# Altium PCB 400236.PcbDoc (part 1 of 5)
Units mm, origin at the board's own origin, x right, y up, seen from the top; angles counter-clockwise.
Board outline 136.53 x 63.5 mm, 4 copper layers (Top Layer, Mid-Layer 1, Mid-Layer 2, Bottom Layer), stack 1.49 mm thick; 344 components, 236 nets, 1364 pads, 1393 vias.
Unrouted connection lines stored in the file: 6.
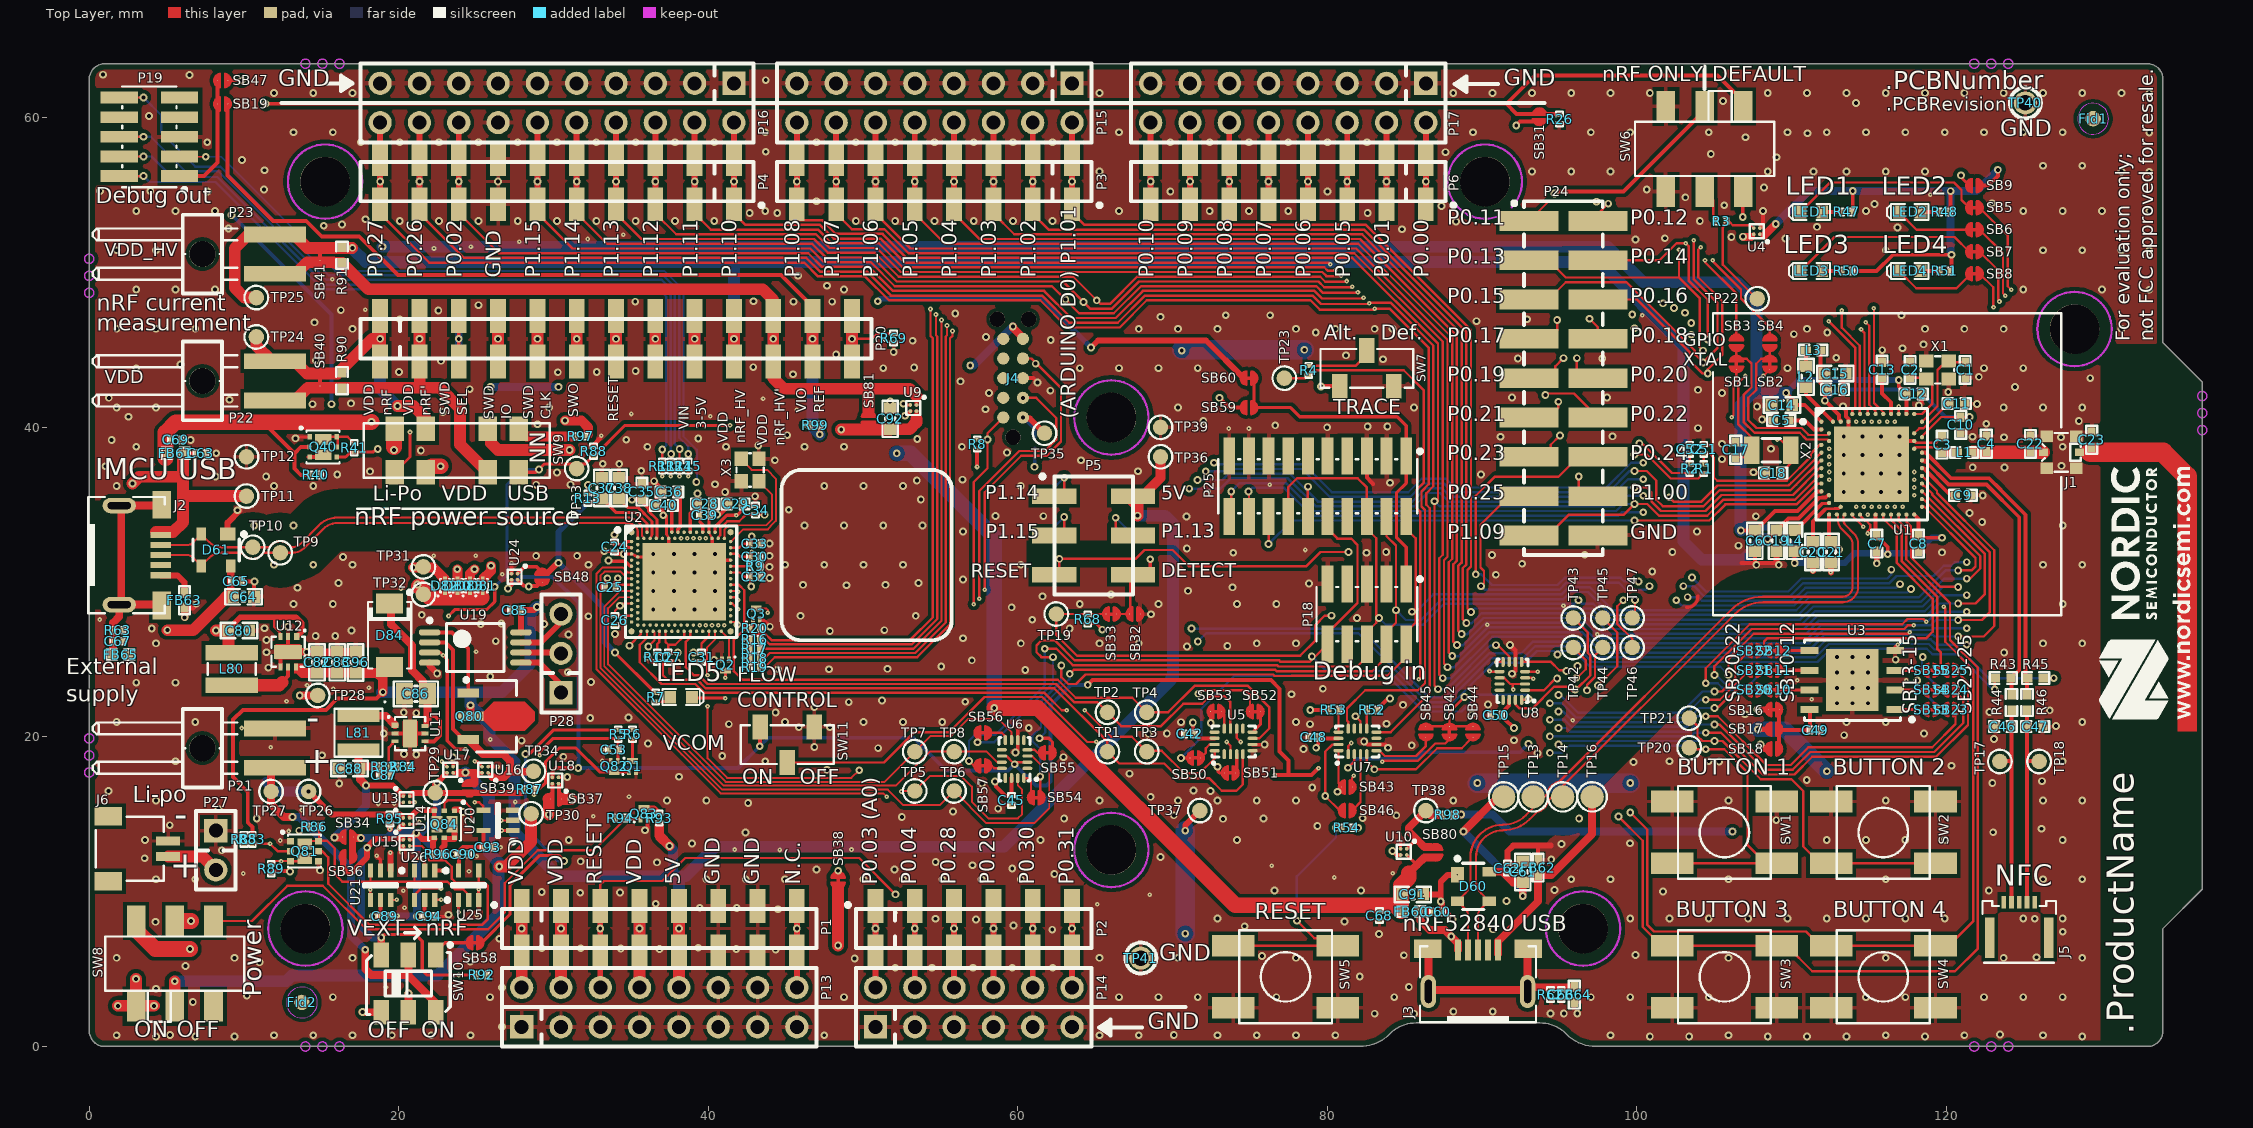
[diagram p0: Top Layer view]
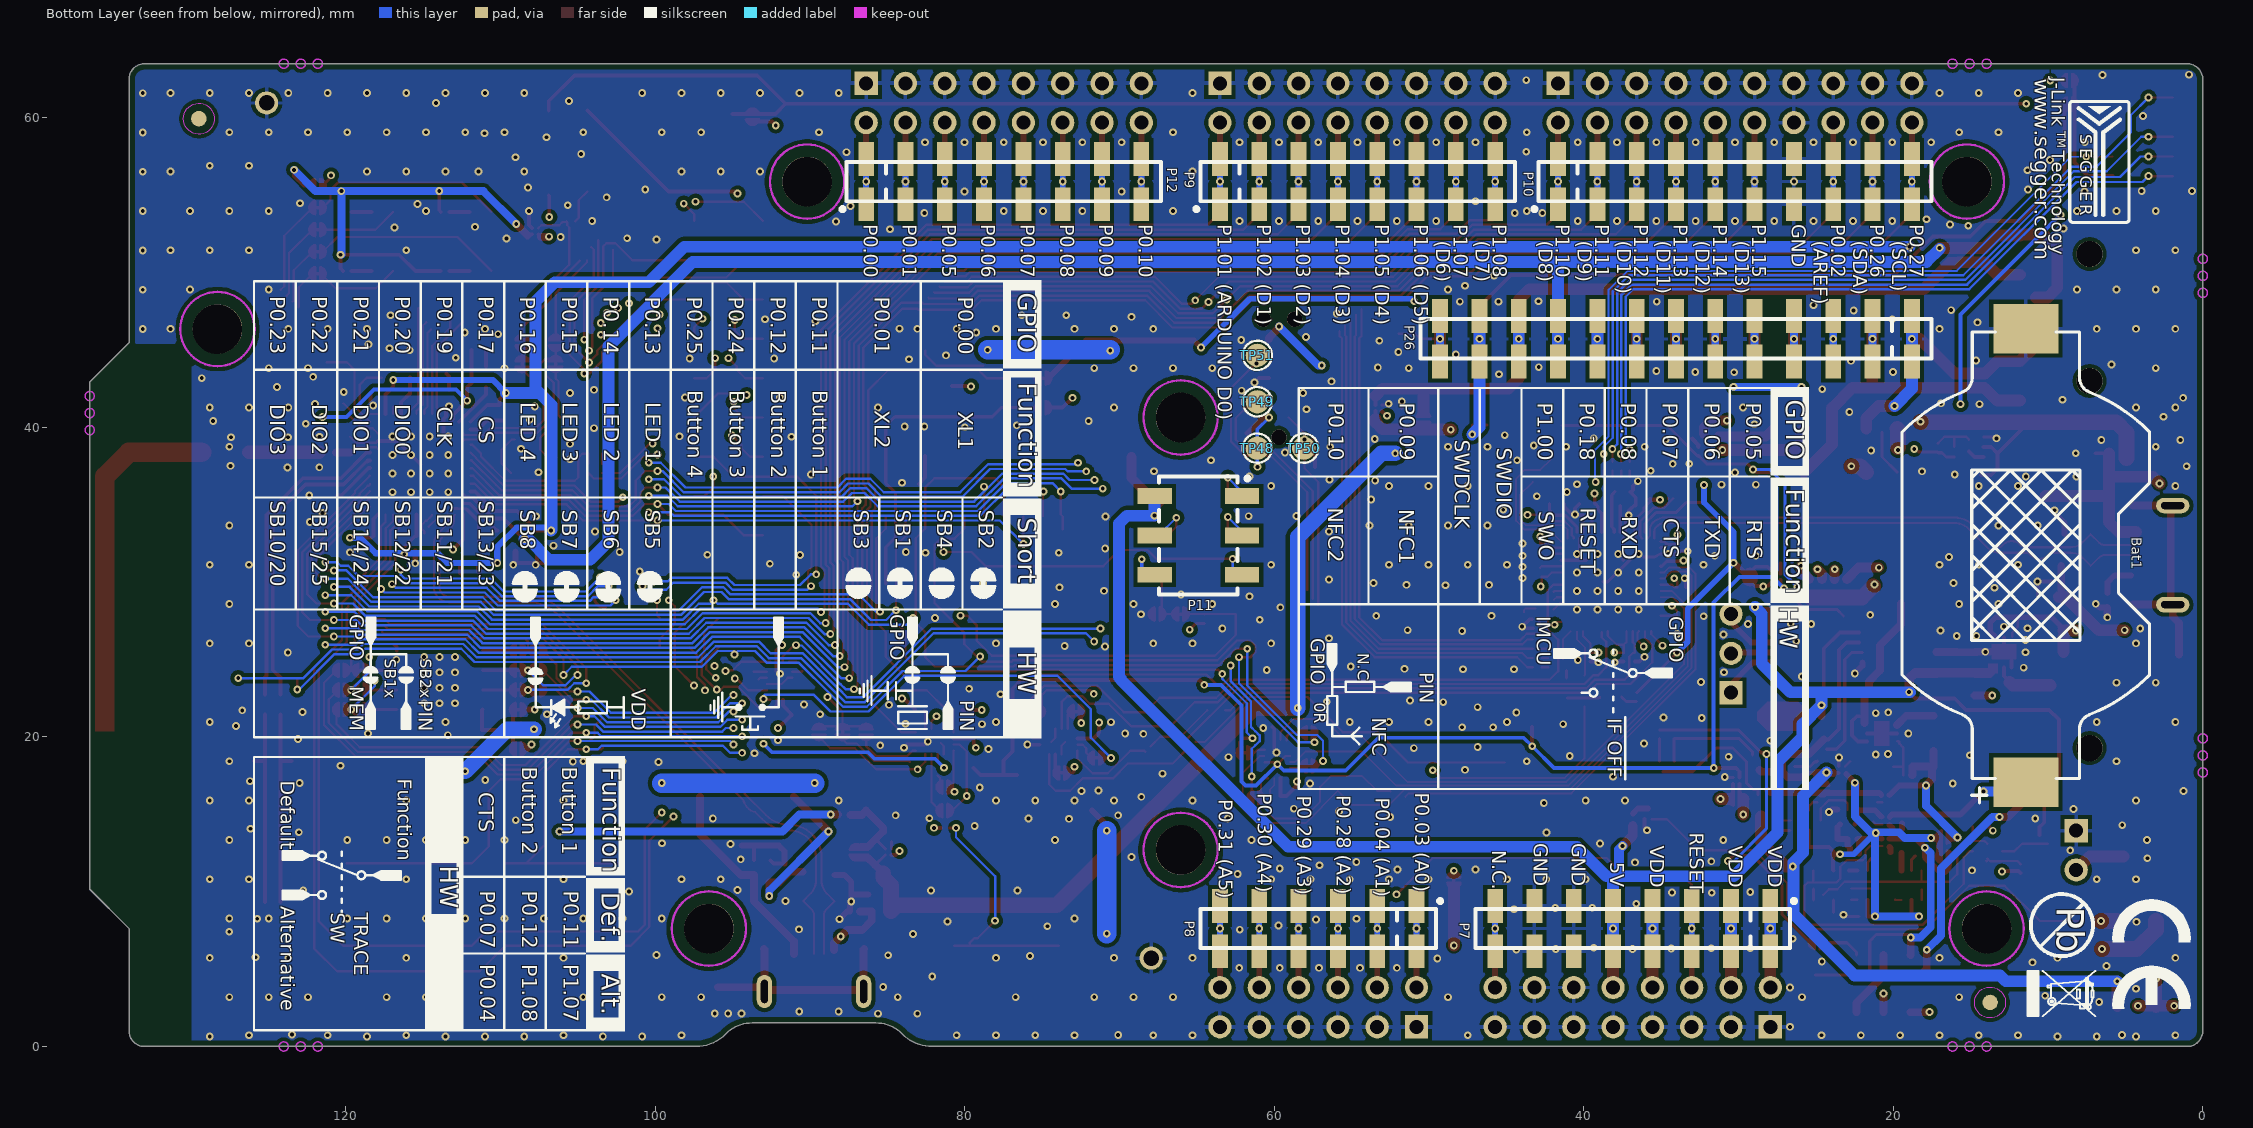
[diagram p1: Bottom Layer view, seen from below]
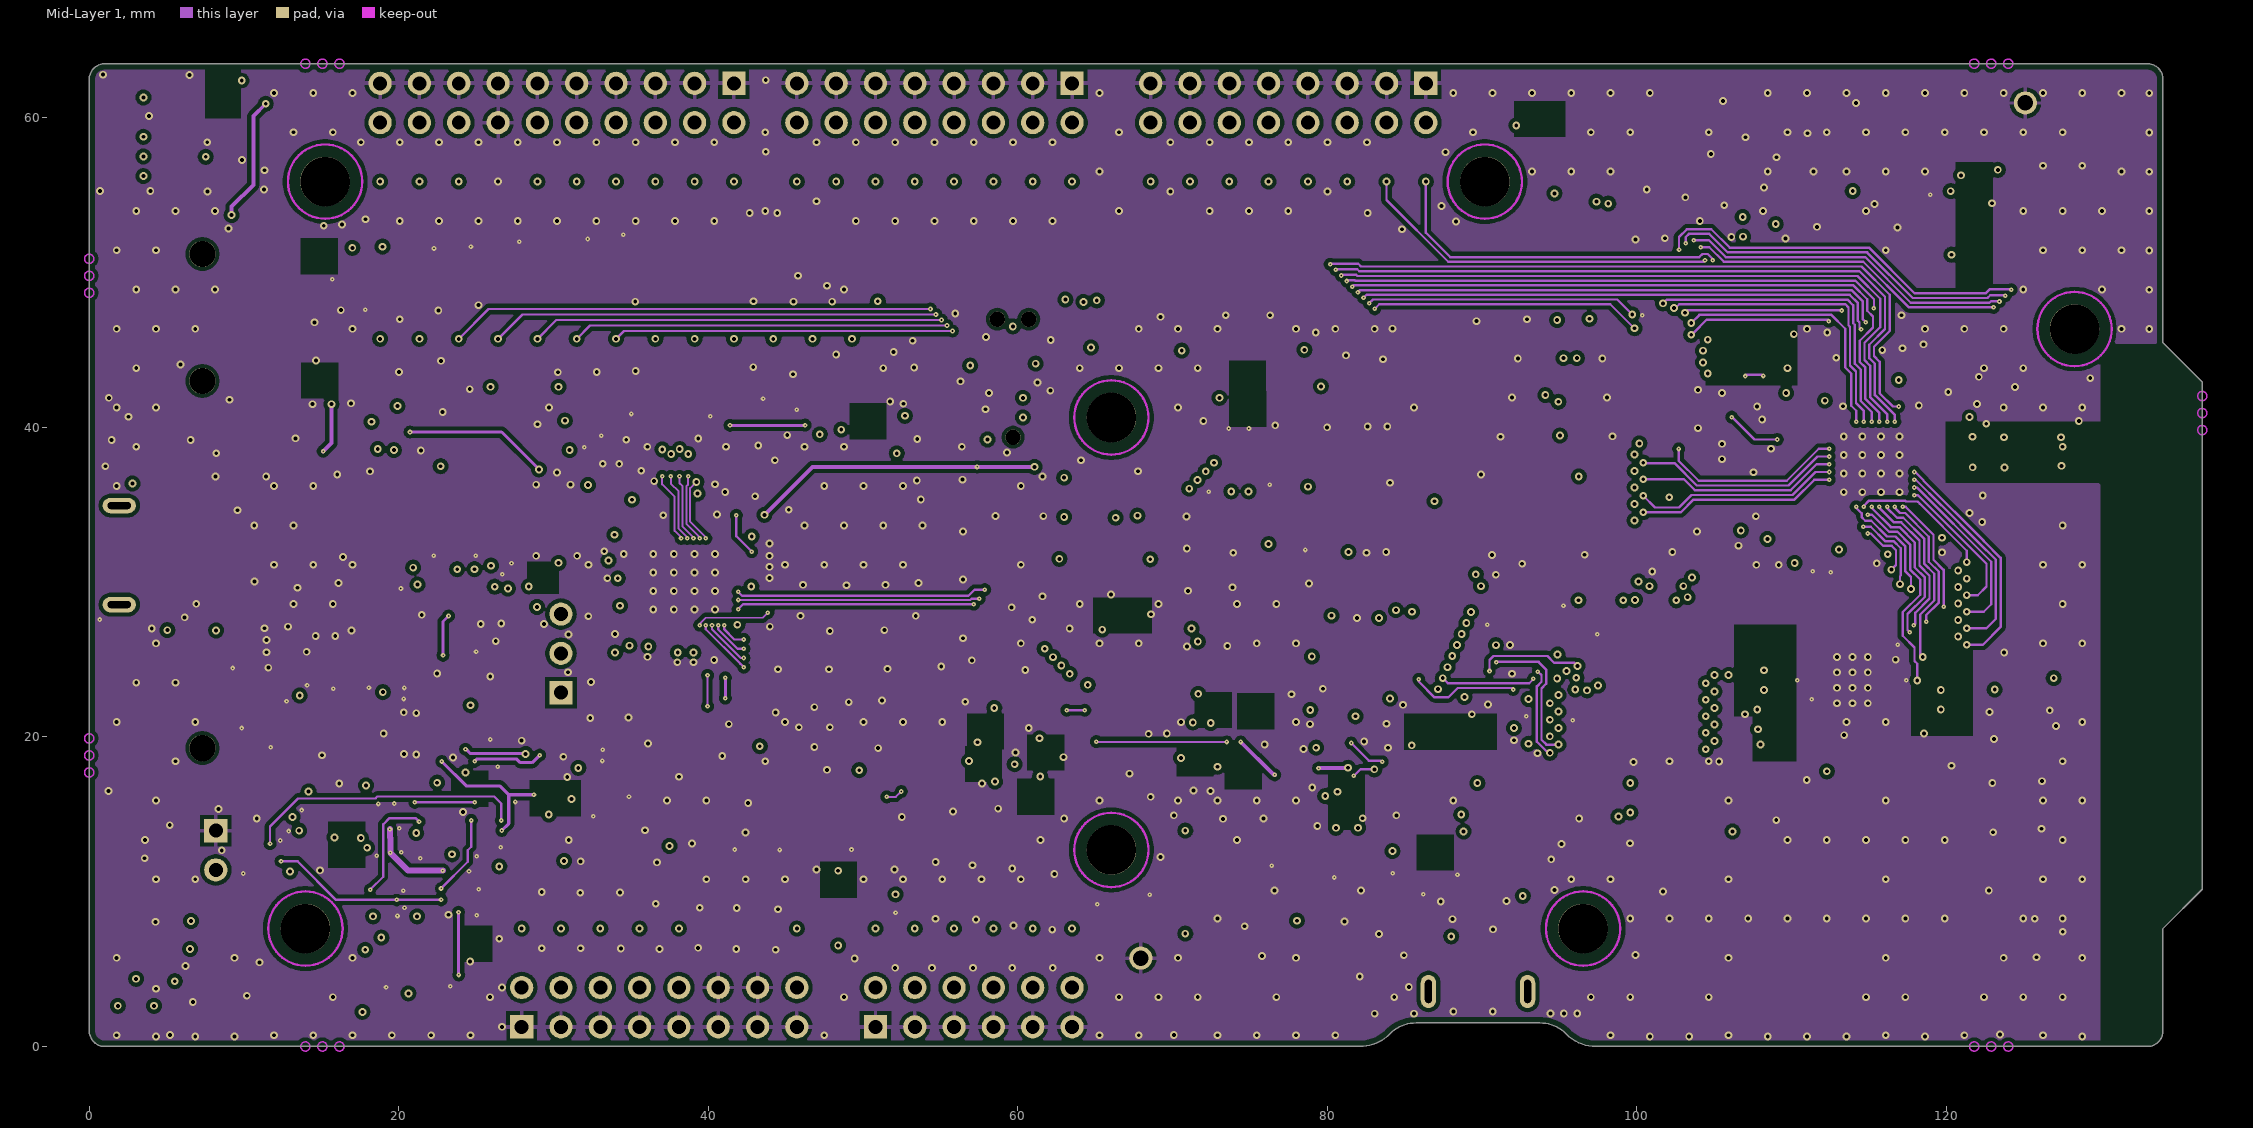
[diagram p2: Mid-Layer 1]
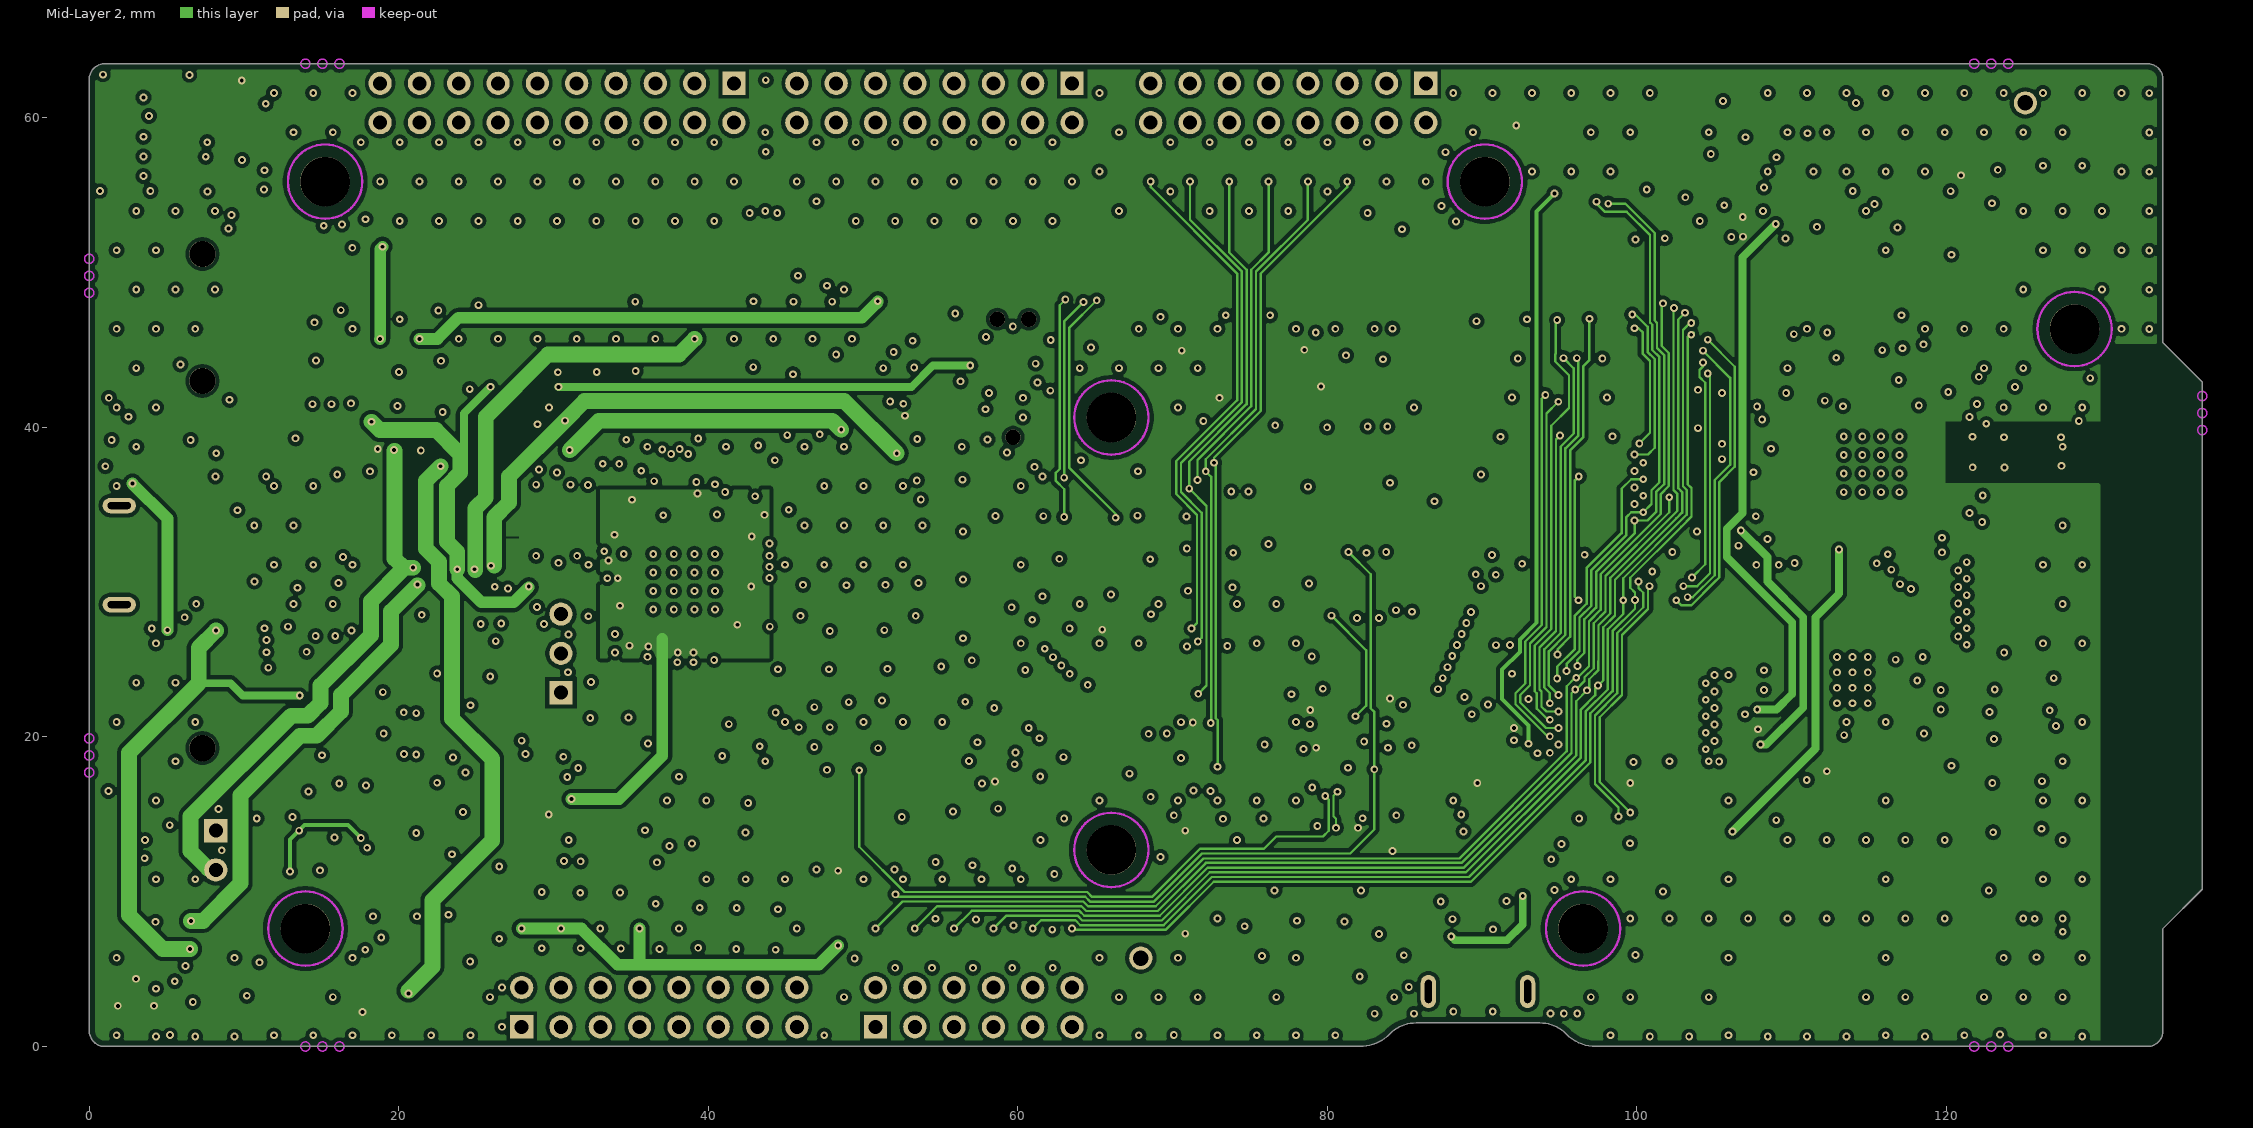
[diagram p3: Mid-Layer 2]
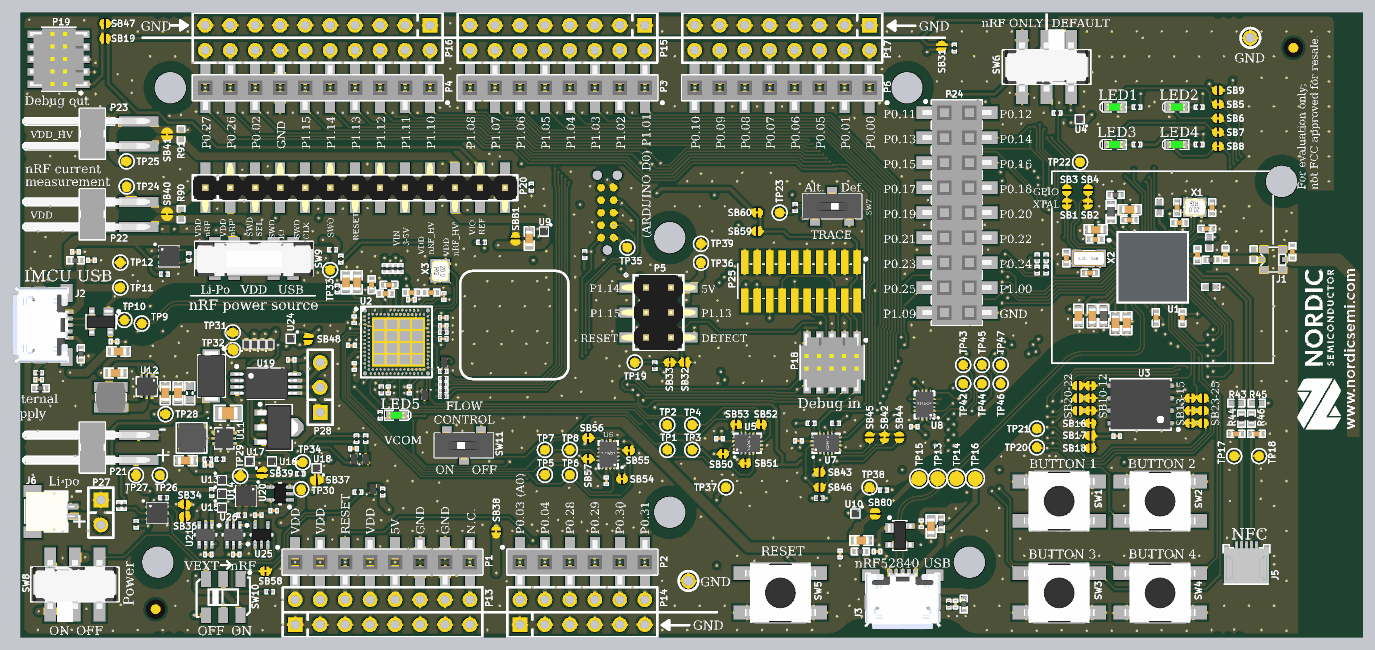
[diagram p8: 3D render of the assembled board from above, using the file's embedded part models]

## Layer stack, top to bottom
Top Solder: solder mask 0.025, Solder Resist, Dk 3.5
Top Layer: signal copper 0.035
Dielectric1: prepreg 0.075, FR-4, Dk 3.72
Mid-Layer 1: signal copper 0.035
Dielectric2: core 1.2, FR-4, Dk 3.72
Mid-Layer 2: signal copper 0.035
Dielectric3: prepreg 0.075, FR-4, Dk 3.72
Bottom Layer: signal copper 0.035
Bottom Solder: solder mask 0.025, Solder Resist, Dk 3.5

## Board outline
1.016,0 82.099,0 ccw(c82.099,2.717) 84.02,0.796 84.187,0.962 cw(c85.729,-0.876) 85.729,1.524 93.729,1.524 cw(c93.729,-0.876) 95.272,0.962 95.439,0.796 ccw(c97.36,2.717) 97.36,0 132.969,0 ccw(c132.969,1.016) 133.985,1.016 133.985,7.62 136.525,10.16 136.525,42.926 133.985,45.466 133.985,62.484 ccw(c132.969,62.484) 132.969,63.5 1.016,63.5 ccw(c1.016,62.484) 0,62.484 0,1.016 ccw(c1.016,1.016)

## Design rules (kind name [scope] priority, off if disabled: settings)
BoardOutlineClearance [All] p1: gap=0.381 ignorepadtopadclearanceinfootprint=FALSE
Clearance Microvia_Clearance [AsMM(ViaDiameter) = 0.3 vs AsMM(ViaDiameter) = 0.3] p1: gap=0.1 ignorepadtopadclearanceinfootprint=FALSE
Clearance USB_Poly_Clearance [InNamedPolygon('Top_Layer-GND') vs InDifferentialPair('D') or InDifferentialPair('IMCU')] p2: gap=1.778 ignorepadtopadclearanceinfootprint=FALSE
Clearance "NPTH clearance" [Not PadIsPlated And HoleSize > 0] p3: gap=0.229 ignorepadtopadclearanceinfootprint=FALSE except(0: Arc-Hole Track-Hole SMDPad-Hole THPad-Hole Via-Hole Fill-Hole Poly-Hole Region-Hole Text-Hole)
Clearance USB_Clearance [(InDifferentialPairClass('All Differential Pairs'))] p4: gap=0.125 ignorepadtopadclearanceinfootprint=FALSE
Clearance ANT_Clerance [InNet('ANT') or InNet('RF')] p5: gap=0.199 ignorepadtopadclearanceinfootprint=FALSE
Clearance Polygon_Clearance [(InNamedPolygon('Top_Layer-GND')) or (InNamedPolygon('Mid_Layer_1-GND')) or (InNamedPolygon('Mid_Layer_2-VDD')) or (InNamedPolygon('Mid_Layer_2-VDD_IMCU')) or (InNamedPolygon('Bottom_Layer-GND'))] p6: gap=0.254 ignorepadtopadclearanceinfootprint=FALSE except(0: Arc-Hole Track-Hole SMDPad-Hole THPad-Hole Via-Hole Fill-Hole Poly-Hole Region-Hole Text-Hole)
Clearance SB_Clearance [HasFootprint('Solderbridge') or HasFootprint('QFN40P180X140X55-10N')] p7: gap=0.127 ignorepadtopadclearanceinfootprint=FALSE except(0: Arc-Hole Track-Hole SMDPad-Hole THPad-Hole Via-Hole Fill-Hole Poly-Hole Region-Hole Text-Hole)
Clearance CSP_Clearance [HasFootprint('BGA4C40P2X2_76X76X62')] p8: gap=0.127 ignorepadtopadclearanceinfootprint=FALSE except(0: Arc-Hole Track-Hole SMDPad-Hole THPad-Hole Via-Hole Fill-Hole Poly-Hole Region-Hole Text-Hole)
Clearance P23_Clearance [HasFootprint('FPC_05P-0.5mm-RA-SMD')] p9: gap=0.127 ignorepadtopadclearanceinfootprint=FALSE except(0: Arc-Hole Track-Hole SMDPad-Hole THPad-Hole Via-Hole Fill-Hole Poly-Hole Region-Hole Text-Hole)
Clearance PSON35P100X50-8N_Clearance [HasFootprint('PSON35P100X50-8N')] p10: gap=0.15 ignorepadtopadclearanceinfootprint=FALSE except(0: Arc-Hole Track-Hole SMDPad-Hole THPad-Hole Via-Hole Fill-Hole Poly-Hole Region-Hole Text-Hole)
Clearance Top_layer_Clearance [All vs OnLayer('Top Layer')] p11: gap=0.125 ignorepadtopadclearanceinfootprint=FALSE
Clearance [All] p12: gap=0.125 ignorepadtopadclearanceinfootprint=FALSE
ComponentClearance [All] p1 off: gap=0.254 collisioncheckmode=3 verticalgap=0.254 showdistances=FALSE
DiffPairsRouting [All] p1: maxlimit=0.193 minlimit=0.191 mostfreqgap=0.193 toplayer_minwidth=0.15 toplayer_maxwidth=0.165 toplayer_prefwidth=0.165 midlayer1_minwidth=0.15 midlayer1_maxwidth=0.165 midlayer1_prefwidth=0.165 midlayer2_minwidth=0.15 midlayer2_maxwidth=0.165 midlayer2_prefwidth=0.165 bottomlayer_minwidth=0.15 bottomlayer_maxwidth=0.165 bottomlayer_prefwidth=0.165 maxuncoupledlength=12.7
FabricationTestPointUsage TestPointUsage [All] p1: valid=0 allowmultiple=FALSE
FabricationTestpoint Testpoint [All] p1: side=3 testpointundercomponent=TRUE minsize=1.016 maxsize=2.54 preferedsize=1.524 minholesize=0 maxholesize=1.016 preferedholesize=0.813 testpointgrid=0.025 allowsidetop=TRUE allowsidebottom=TRUE usegrid=TRUE gridtolerance=0
Height [All] p1 off: minheight=0 maxheight=25.4 prefheight=12.7
HoleSize [All] p1: absolutevalues=TRUE maxlimit=5 minlimit=0.1 maxpercent=80.000 minpercent=20.000
MinimumAnnularRing [All] p1 off: minimumring=0.152
NetAntennae NetAntennae_ANT [InNet('ANT')] p1: netantennaetolerance=40
NetAntennae [All] p2 off: netantennaetolerance=0
PolygonConnect PolygonConnect_1 [isVia and innet(gnd) or isVia and innet('VDD') or HasFootprint('COAXIAL-SWF') or isVia and innet('VDD_IMCU')] p1: connectstyle=Direct reliefconductorwidth=0.254 reliefentries=4 polygonreliefangle="90 Angle" airgapwidth=0.254
PolygonConnect [All] p2: connectstyle=Relief reliefconductorwidth=0.254 reliefentries=4 polygonreliefangle="90 Angle" airgapwidth=0.254
RoutingVias [All] p1: holewidth=0.25 width=0.5 viastyle="Through Hole" minholewidth=0.1 minwidth=0.3 maxholewidth=0.305 maxwidth=0.61
SilkToSolderMaskClearance SilkscreenOverComponentPads [IsPad] p1: minsilkscreentomaskgap=0.254 clearancetoexposedcopper=TRUE
SolderMaskExpansion SolderMaskExpansion_1 [isVia] p1: expansion=0.102 istentingtop=TRUE
SolderMaskExpansion [All] p2: expansion=0.076 istentingtop=FALSE
UnpouredPolygon [All] p1 off:
Width Width_Diff [(InDifferentialPairClass('All Differential Pairs'))] p1: maxlimit=0.165 minlimit=0.165 preferedwidth=0.165
Width [All] p2: maxlimit=10.16 minlimit=0.102 preferedwidth=0.152 minimp=50.000000 maximp=50.000000 favimp=50.000000
21 further rules are at their usual default settings.

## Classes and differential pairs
component class pca10056_sheet6_power_supply: Bat1 C53 C80 C82 C83 C85 C86 C87 C88 C89 C90 C91 C92 C93 C94 C96 D80 D81 D82 D83 D84 L80 L81 P21 P22 P23 Q1 Q80 Q81 Q82 Q83 Q84 R5 R6 R82 R83 R84 R85 R86 R87 R88 R89 R90 R91 R92 R93 R94 R95 R96 R97 R98 R99 SB34 SB36 SB37 SB38 SB39 SB40 SB41 SB48 SB58 SB80 SB81 SW8 SW9 SW10 TP24 TP25 TP26 TP27 TP28 TP29 TP30 TP32 TP33 TP34 TP35 TP36 TP37 TP38 TP39 TP40 TP41 U9 U10 U11 U12 U13 U14 U15 U16 U17 U18 U19 U20 U21 U24 U25 U26
component class pca10056_sheet5_connectors: C60 C61 C62 C63 C64 C65 C66 C67 C68 C69 D60 D61 FB60 FB61 FB62 FB63 FB64 FB65 J2 J3 J5 J6 P1 P2 P3 P4 P5 P6 P7 P8 P9 P10 P11 P12 P13 P14 P15 P16 P17 P18 P19 P20 P24 P25 P26 P27 R62 R63 R68 R69 SB19 SB32 SB33 SB47 SB59 SB60 TP9 TP10 TP11 TP12 TP13 TP14 TP15 TP16 TP17 TP18 TP19 TP31 TP42 TP43 TP44 TP45 TP46 TP47
component class pca10056_sheet4_misc: C42 C45 C46 C47 C48 C49 C50 LED1 LED2 LED3 LED4 P28 Q40 R3 R4 R26 R40 R41 R44 R46 R47 R48 R50 R51 R52 R53 R54 SB5 SB6 SB7 SB8 SB9 SB16 SB17 SB18 SB31 SB42 SB43 SB44 SB45 SB46 SB50 SB51 SB52 SB53 SB54 SB55 SB56 SB57 SW1 SW2 SW3 SW4 SW5 SW6 SW7 SW11 TP1 TP2 TP3 TP4 TP5 TP6 TP7 TP8 TP20 TP21 TP22 TP23 U3 U4 U5 U6 U7 U8
component class pca10056_sheet3_interface_mcu: C24 C25 C26 C27 C28 C29 C30 C31 C32 C33 C34 C35 C36 C37 C38 C39 C40 J4 LED5 Q2 Q3 R7 R8 R9 R10 R11 R12 R13 R14 R15 R16 R17 R18 R19 R20 TP48 TP49 TP50 TP51 U2 X3
differential pair IMCU: +IMCU_P -IMCU_N
differential pair D: +D_P -D_N

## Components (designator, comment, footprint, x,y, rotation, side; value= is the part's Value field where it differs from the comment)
Bat1 "Bat Holder CR2032" L-KLS5-CR2032-23-B1 11.43,31.735 r90 bottom locked
C1 "12pF" CAPC1005X04L 121.203,43.713 r270 top
C2 "12pF" CAPC1005X04L 117.647,43.713 r90 top
C3 "0.8pF" CAPC1005X04L 119.715,38.893 r270 top
C4 "0.5pF" CAPC1005X04L 122.57,38.938 r270 top
C5 "100nF" CAPC1005X04L 109.324,40.455 r180 top
C6 "4.7µF" CAPC1608X06L 107.613,32.667 r270 top
C7 "100nF" CAPC1005X04L 115.49,32.492 r270 top
C8 "100nF" CAPC1005X04L 118.189,32.492 r270 top
C9 "N.C." CAPC1005X04L_NC 121.064,35.617 r0 top
C10 "N.C." CAPC1005X04L_NC 120.919,40.157 r90 top
C11 "100pF" CAPC1005X04L 120.664,41.542 r0 top
C12 "100nF" CAPC1005X04L 117.889,42.167 r0 top
C13 "N.C." CAPC1005X04L_NC 115.839,43.717 r90 top
C14 "1.0µF" CAPC1608X06L 109.364,41.444 r180 top
C15 "1.0µF" CAPC1608X06L 112.814,43.481 r180 top
C16 "47nF" CAPC1005X04L 112.801,42.443 r0 top
C17 "12pF" CAPC1005X04L 106.385,38.55 r270 top
C18 "12pF" CAPC1005X04L 108.798,37.052 r0 top
C19 "4.7µF" CAPC1608X06L 109.014,32.667 r270 top
C20 "4.7µF" CAPC1608X06L 111.364,31.942 r270 top
C21 "4.7µF" CAPC1608X06L 112.539,31.942 r270 top
C22 "N.C." CAPC1005X04L_NC 125.423,38.935 r90 top
C23 "1.2pF" CAPC1005X04L 129.379,39.204 r90 top
C24 "100nF" CAPC0603X03L_C 33.939,32.277 r270 top
C25 "100nF" CAPC0603X03L_C 33.664,29.677 r180 top
C26 "100nF" CAPC0603X03L_C 33.964,27.527 r270 top
C27 "100nF" CAPC0603X03L_C 37.415,25.152 r270 top
C28 "1.0µF" CAPC1005X04L 39.789,35.052 r0 top
C29 "1.0µF" CAPC1005X04L 41.764,35.052 r0 top
C30 "2.2nF" CAPC0603X03L_C 43,31.652 r0 top
C31 "100nF" CAPC0603X03L_C 39.564,25.152 r270 top
C32 "100nF" CAPC0603X03L_C 43,30.352 r0 top
C33 "100nF" CAPC0603X03L_C 43,32.491 r0 top
C34 "100nF" CAPC0603X03L_C 43.05,34.65 r90 top
C35 "1.0µF" CAPC1005X04L 35.714,35.852 r270 top
C36 "1.0µF" CAPC1005X04L 37.489,35.832 r0 top
C37 "4.7µF" CAPC1608X06L 33.114,36.082 r90 top
C38 "4.7µF" CAPC1608X06L 34.239,36.082 r90 top
C39 "100nF" CAPC0603X03L_C 39.758,34.327 r0 top
C40 "1.0µF" CAPC1005X04L 37.139,34.957 r0 top
C42 "100nF" CAPC0603X03L_C 71.095,20.193 r0 top
C45 "100nF" CAPC0603X03L_C 59.588,15.9 r90 top
C46 "300pF" CAPC1005X04L 123.647,20.669 r180 top
C47 "300pF" CAPC1005X04L 125.73,20.669 r180 top
C48 "100nF" CAPC0603X03L_C 79.121,19.964 r0 top
C49 "100nF" CAPC0603X03L_C 111.506,20.447 r180 top
C50 "100nF" CAPC0603X03L_C 90.907,21.412 r0 top
C51 "N.C." CAPC0603X03L_C_NC 104.318,38.583 r270 top
C52 "N.C." CAPC0603X03L_C_NC 103.403,38.583 r270 top
C53 "10nF" CAPC0603X03L_C 33.875,19.175 r0 top
C60 "10nF" CAPC0603X03L_C 87.122,8.712 r180 top
C61 "10µF" CAPC1608X06L 92.623,11.278 r270 top
C62 "100nF" CAPC0603X03L_C 91.632,11.532 r270 top
C63 "10nF" CAPC0603X03L_C 7.219,38.329 r0 top
C64 "10µF" CAPC1608X06L 9.972,29.058 r180 top
C65 "100nF" CAPC0603X03L_C 9.515,30.074 r180 top
C66 "4.7nF" CAPC0603X03L_C 95.104,3.355 r90 top
C67 "4.7nF" CAPC0603X03L_C 1.85,26.187 r180 top
C68 "100nF" CAPC0603X03L_C 83.363,8.458 r90 top
C69 "100nF" CAPC0603X03L_C 5.588,39.192 r180 top
C80 "10µF" CAPC1608X06L 9.675,26.875 r180 top
C82 "10µF" CAPC1608X06L 14.725,24.825 r270 top
C83 "10µF" CAPC1608X06L 16.025,24.825 r270 top
C85 "100nF" CAPC0603X03L_C 27.534,28.194 r0 top
C86 "4.7µF" CAPC2012X11L 21.107,22.784 r0 top
C87 "150pF" CAPC0603X03L_C 19.075,17.526 r180 top
C88 "10µF" CAPC1608X06L 16.815,17.958 r0 top
C89 "100nF" CAPC0603X03L_C 19.101,8.407 r180 top
C90 "100nF" CAPC0603X03L_C 24.181,12.421 r180 top
C91 "1.0µF" CAPC1608X06L 85.522,9.83 r180 top
C92 "1.0µF" CAPC1608X06L 51.75,40.55 r270 top
C93 "100nF" CAPC0603X03L_C 25.756,12.878 r180 top
C94 "100nF" CAPC0603X03L_C 21.946,8.407 r180 top
C96 "N.C." CAPC1608X06L_NC 17.215,24.815 r270 top
D60 "PRTR5V0U2X" SOT190P230X110-4L 89.427,10.34 r0 top
D61 "PRTR5V0U2X" SOT190P230X110-4L 8.194,32.08 r270 top
D80 "NSR0620P2T5G" SODFL100X40-2N 23.8,29.766 r90 top
D81 "NSR0620P2T5G" SODFL100X40-2N 25.425,29.766 r90 top
D82 "NSR0620P2T5G" SODFL100X40-2N 22.987,29.766 r90 top
D83 "NSR0620P2T5G" SODFL100X40-2N 24.613,29.766 r90 top
D84 "LS14" SODFL500X108-2N 19.407,26.568 r270 top
FB60 "120R/0.55A" INDC1005X04L 85.42,8.712 r180 top
FB61 "120R/0.55A" INDC1005X04L 5.588,38.329 r180 top
FB62 "120R/0.55A" INDC1005X04L 93.614,11.558 r90 top
FB63 "120R/0.55A" INDC1005X04L 6.147,28.829 r270 top
FB64 "120R/0.55A" INDC1005X04L 95.942,3.355 r270 top
FB65 "120R/0.55A" INDC1005X04L 2.021,25.317 r0 top
Fid1 "Fiducial mark" Fiducial 129.471,59.944 r180 top value=N.A.
Fid2 "Fiducial mark" Fiducial 13.743,2.845 r0 top value=N.A.
J1 "MM8130-2600" COAXIAL-SWF 127.423,38.391 r90 top
J2 "MicroUSB-B" USB-Micro-B-RA-SMD-PiP_Allen 4.619,31.75 r0 top
J3 "MicroUSB-B" USB-Micro-B-RA-SMD-PiP_Allen 89.729,6.232 r90 top
J4 "TC2050-IDC" TC2050-IDC-NLFP 59.69,43.18 r90 top locked
J5 "FPC 0.5mm RA SMD" FPC_05P-0.5mm-RA-SMD 123.698,9.328 r0 top
J6 "HDR-2, 1mm" SM02B-SRSS-TB 5.105,12.776 r270 top
L1 "4.7nH" INDC1005X04L 121.138,38.385 r0 top
L2 "10µH" INDC1608X06L 110.914,43.267 r270 top
L3 "15nH" INDC1005X04L 111.389,44.992 r180 top
L4 "10µH" INDC1608X06L 110.189,32.667 r90 top
L80 "4.7µH" VLS3012HBX 9.2,24.4 r270 top
L81 "4.7µH" TY-NR3015 17.399,20.269 r270 top
LED1 "L0603G" LED_0603_G 111.273,53.917 r0 top
LED2 "L0603G" LED_0603_G 117.623,53.917 r0 top
LED3 "L0603G" LED_0603_G 111.273,50.107 r0 top
LED4 "L0603G" LED_0603_G 117.623,50.107 r0 top
LED5 "L0603G" LED_0603_G 38.239,22.575 r180 top
P1 "Socket 1x8" SOCKET_1x8_SMD 27.94,7.62 r0 top locked
P2 "Socket 1x6" SOCKET_1x6_SMD 50.8,7.62 r0 top locked
P3 "Socket 1x8" SOCKET_1x8_SMD 63.5,55.88 r180 top locked
P4 "Socket 1x10" SOCKET_1x10_SMD 41.656,55.88 r180 top locked
P5 "Pin Hdr 2x3" HDR_2x3-SMD 64.897,33.02 r270 top locked
P6 "Socket 1x8" SOCKET_1x8_SMD 86.36,55.88 r180 top locked
P7 "Pin List 1x8" LIST_1x8_SMD-NC 27.94,7.62 r0 bottom locked
P8 "Pin List 1x6" LIST_1x6_SMD-NC 50.8,7.62 r0 bottom locked
P9 "Pin List 1x8" LIST_1x8_SMD-NC 63.5,55.88 r180 bottom locked
P10 "Pin List 1x10" LIST_1x10_SMD-NC 41.656,55.88 r180 bottom locked
P11 "Socket 2x3" SOCKET_2x3_SMD-2.54mm-NC 64.897,33.02 r90 bottom
P12 "Pin List 1x8" LIST_1x8_SMD-NC 86.36,55.88 r180 bottom locked
P13 "Pin Header 2x8" HDR_2x8-NC 36.83,2.54 r0 top locked
P14 "Pin Header 2x6" HDR_2x6-NC 57.15,2.54 r0 top locked
P15 "Pin Header 2x8" HDR_2x8-NC 54.61,60.96 r180 top locked
P16 "Pin Header 2x10" HDR_2x10-NC 30.226,60.96 r180 top locked
P17 "Pin Header 2x8" HDR_2x8-NC 77.47,60.96 r180 top locked
P18 "Pin Header 2x5, 1.27mm" HDR_2x5-SMD-1.27mm-K 82.55,27.94 r180 top locked
P19 "Pin Header 2x5, 1.27mm" HDR_2x5-SMD-1.27mm-K 3.886,58.776 r90 top
P20 "Pin List 1x13" LIST_1x13_SMD 18.796,45.72 r0 top locked
P21 "Pin List 1x2, Angled" LIST_ANG_1x2-SMD-2.54MM 11.811,19.279 r270 top
P22 "Pin List 1x2, Angled" LIST_ANG_1x2-SMD-2.54MM 11.811,43 r270 top
P23 "Pin List 1x2, Angled" LIST_ANG_1x2-SMD-2.54MM 11.811,51.2 r270 top
P24 "Socket 2x9" SOCKET_2x9_SMD-2.54mm-Mirrored 95.25,43.18 r270 top locked
P25 "Pin Header 2x10, 1.27mm" HDR_2x10-SMD-1.27mm-NC 79.375,36.195 r180 top locked
P26 "Socket 1x13" LIST_1x13_SMD-NC 18.796,45.72 r0 bottom locked
P27 "Pin List 1x2" LIST_1x2-NC 8.179,12.675 r270 top locked
P28 "Pin List 1x3" LIST_1x3-NC 30.48,25.4 r90 top locked
Q1 "RV2C010UNT2L" DFN65P100X40-3L 35.1,18.1 r90 top
Q2 "RV2C010UNT2L" DFN65P100X40-3L 41.1,24.65 r270 top
Q3 "RV2C010UNT2L" DFN65P100X40-3L 43.1,27.95 r90 top
Q40 "PMCPB5530" PMCPB5530X 15.113,38.735 r0 top
Q80 "FCX690BTA" SOT89-150P409X160-3N 26.289,21.336 r0 top
Q81 "TSM250N02DCQ RFG" DFN65P200X200X80_HS-6N 13.919,12.624 r0 top
Q82 "RV2C010UNT2L" DFN65P100X40-3L 33.925,18.1 r270 top
Q83 "RV2C010UNT2L" DFN65P100X40-3L 35.839,15.037 r90 top
Q84 "PMCPB5530" PMCPB5530X 22.951,14.356 r270 top
R1 "0R" RESC0603X03L_C 104.318,37.338 r90 top
R2 "0R" RESC0603X03L_C 103.403,37.338 r90 top
R3 "10k" RESC0603X03L_C 105.435,53.315 r180 top
R4 "10k" RESC0603X03L_C 78.791,43.688 r90 top
R5 "10M" RESC0603X03L_C 34.175,20.175 r270 top
R6 "47k" RESC0603X03L_C 35.1,20.175 r90 top
R7 "560R" RESC0603X03L_C 36.6,22.575 r90 top
R8 "100k" RESC0603X03L_C 57.375,38.925 r270 top
R9 "49.9R" RESC0603X03L_C 43,31.017 r0 top
R10 "N.C." RESC0603X03L_C_NC 36.7,25.15 r270 top
R11 "150R" RESC0603X03L_C 37.021,37.494 r90 top
R12 "150R" RESC0603X03L_C 37.579,37.494 r90 top
R13 "2R2" RESC0603X03L_C 32.225,35.425 r270 top
R14 "150R" RESC0603X03L_C 38.138,37.494 r90 top
R15 "150R" RESC0603X03L_C 38.697,37.494 r90 top
R16 "150R" RESC0603X03L_C 43,26.3 r0 top
R17 "150R" RESC0603X03L_C 43,25.7 r0 top
R18 "150R" RESC0603X03L_C 43,25.1 r0 top
R19 "150R" RESC0603X03L_C 43,24.5 r0 top
R20 "1M0" RESC0603X03L_C 43,27.025 r0 top
R26 "47k" RESC0603X03L_C 94.996,59.919 r270 top
R40 "150k" RESC0603X03L_C 14.63,36.932 r0 top
R41 "1M0" RESC0603X03L_C 17.12,38.684 r90 top
R43 "N.C." RESC1005X04L_NC 123.669,23.8 r0 top
R44 "0R" RESC1005X04L 124.206,22.225 r90 top
R45 "N.C." RESC1005X04L_NC 125.751,23.8 r180 top
R46 "0R" RESC1005X04L 125.197,22.225 r90 top
R47 "220R" RESC0603X03L_C 113.559,53.917 r0 top
R48 "220R" RESC0603X03L_C 119.884,53.917 r0 top
R50 "220R" RESC0603X03L_C 113.559,50.107 r0 top
R51 "220R" RESC0603X03L_C 119.884,50.107 r0 top
R52 "4k7" RESC0603X03L_C 82.906,21.742 r180 top
R53 "4k7" RESC0603X03L_C 80.416,21.742 r0 top
R54 "N.C." RESC0603X03L_C_NC 81.25,14.125 r0 top
R62 "1M0" RESC0603X03L_C 94.418,3.355 r90 top
R63 "1M0" RESC0603X03L_C 1.85,26.899 r180 top
R68 "1M0" RESC0603X03L_C 64.516,27.61 r270 top
R69 "866R" RESC0603X03L_C 51.968,45.771 r90 top
R82 "330k" RESC0603X03L_C 19.05,18.085 r180 top
R83 "820k" RESC0603X03L_C 10.538,13.386 r270 top
R84 "120k" RESC0603X03L_C 20.295,18.085 r180 top
R85 "470k" RESC0603X03L_C 10.004,13.386 r90 top
R86 "1M0" RESC0603X03L_C 14.55,14.2 r0 top
R87 "1M0" RESC0603X03L_C 28.448,16.612 r0 top
R88 "10M" RESC0603X03L_C 32.588,38.456 r90 top
R89 "1M0" RESC0603X03L_C 11.76,11.481 r90 top
R90 "N.C." RESC1005X04L_NC 16.332,43.025 r90 top
R91 "N.C." RESC1005X04L_NC 16.332,51.13 r90 top
R92 "10M" RESC0603X03L_C 25.349,4.623 r0 top
R93 "1k" RESC0603X03L_C 36.83,14.757 r90 top
R94 "10M" RESC0603X03L_C 34.315,14.757 r180 top
R95 "100k" RESC0603X03L_C 19.431,14.707 r270 top
R96 "1M0" RESC0603X03L_C 22.504,12.421 r0 top
R97 "4R7" RESC0603X03L_C 31.75,39.421 r180 top
R98 "4R7" RESC0603X03L_C 87.782,14.961 r0 top
R99 "10k" RESC0603X03L_C 46.9,40.15 r0 top
SB1 "Solderbridge" Solderbridge_Shorted 106.426,44.094 r90 top net-tie
SB2 "Solderbridge" Solderbridge_Shorted 108.585,44.094 r90 top net-tie
SB3 "Solderbridge" Solderbridge 106.426,45.466 r90 top
SB4 "Solderbridge" Solderbridge 108.585,45.466 r90 top
SB5 "Solderbridge" Solderbridge_Shorted 121.801,54.197 r180 top net-tie
SB6 "Solderbridge" Solderbridge_Shorted 121.801,52.774 r180 top net-tie
SB7 "Solderbridge" Solderbridge_Shorted 121.801,51.352 r180 top net-tie
SB8 "Solderbridge" Solderbridge_Shorted 121.801,49.93 r180 top net-tie
SB9 "Solderbridge" Solderbridge 121.802,55.619 r0 top
SB10 "Solderbridge" Solderbridge_Shorted 108.839,23.038 r0 top net-tie
SB11 "Solderbridge" Solderbridge_Shorted 108.839,24.308 r0 top net-tie
SB12 "Solderbridge" Solderbridge_Shorted 108.839,25.578 r0 top net-tie
SB13 "Solderbridge" Solderbridge_Shorted 118.999,21.768 r180 top net-tie
SB14 "Solderbridge" Solderbridge_Shorted 118.999,23.038 r180 top net-tie
SB15 "Solderbridge" Solderbridge_Shorted 118.999,24.308 r180 top net-tie
SB16 "Solderbridge" Solderbridge_Shorted 108.839,21.768 r0 top net-tie
SB17 "Solderbridge" Solderbridge 108.839,20.498 r0 top
SB18 "Solderbridge" Solderbridge 108.839,19.228 r0 top
SB19 "Solderbridge" Solderbridge 8.611,60.9 r0 top
SB20 "Solderbridge" Solderbridge 107.569,23.038 r180 top
SB21 "Solderbridge" Solderbridge 107.569,24.308 r180 top
SB22 "Solderbridge" Solderbridge 107.569,25.578 r180 top
SB23 "Solderbridge" Solderbridge 120.269,21.768 r0 top
SB24 "Solderbridge" Solderbridge 120.269,23.038 r0 top
SB25 "Solderbridge" Solderbridge 120.269,24.308 r0 top
SB31 "Solderbridge" Solderbridge 93.701,60.071 r90 top
SB32 "Solderbridge" Solderbridge 67.564,27.94 r180 top
SB33 "Solderbridge" Solderbridge_Shorted 66.04,27.94 r180 top net-tie
SB34 "Solderbridge" Solderbridge 16.709,13.535 r180 top
SB36 "Solderbridge" Solderbridge 16.709,12.265 r180 top
SB37 "Solderbridge" Solderbridge 30.144,15.992 r180 top
SB38 "Solderbridge" Solderbridge_Shorted 48.387,10.744 r90 top net-tie
SB39 "Solderbridge" Solderbridge 24.562,16.688 r270 top
SB40 "Solderbridge" Solderbridge_Shorted 14.91,43.025 r270 top net-tie
SB41 "Solderbridge" Solderbridge_Shorted 14.91,51.13 r270 top net-tie
SB42 "Solderbridge" Solderbridge_Shorted 87.884,20.32 r90 top net-tie
SB43 "Solderbridge" Solderbridge 81.28,16.764 r0 top
SB44 "Solderbridge" Solderbridge 89.408,20.32 r90 top
SB45 "Solderbridge" Solderbridge 86.36,20.32 r90 top
SB46 "Solderbridge" Solderbridge 81.28,15.24 r180 top
SB47 "Solderbridge" Solderbridge 8.611,62.408 r180 top
SB48 "Solderbridge" Solderbridge 29.261,30.324 r270 top
SB50 "Solderbridge" Solderbridge_Shorted 71.476,18.644 r0 top net-tie
SB51 "Solderbridge" Solderbridge_Shorted 73.725,17.675 r0 top net-tie
SB52 "Solderbridge" Solderbridge_Shorted 75.336,21.641 r0 top net-tie
SB53 "Solderbridge" Solderbridge_Shorted 72.796,21.641 r0 top net-tie
SB54 "Solderbridge" Solderbridge_Shorted 61.189,16.078 r180 top net-tie
SB55 "Solderbridge" Solderbridge_Shorted 61.9,18.974 r180 top net-tie
SB56 "Solderbridge" Solderbridge_Shorted 57.734,20.269 r0 top net-tie
SB57 "Solderbridge" Solderbridge_Shorted 57.734,18.136 r0 top net-tie
SB58 "Solderbridge" Solderbridge_Shorted 24.917,6.706 r180 top net-tie
SB59 "Solderbridge" Solderbridge 74.93,41.275 r180 top
SB60 "Solderbridge" Solderbridge_Shorted 74.93,43.18 r180 top net-tie
SB80 "Solderbridge" Solderbridge 86.995,12.548 r270 top
SB81 "Solderbridge" Solderbridge 50.35,40.525 r270 top
SW1 "PB SW" Switch-PB-6.2x6.3mm-SMD 105.653,13.83 r0 top locked
SW2 "PB SW" Switch-PB-6.2x6.3mm-SMD 115.915,13.83 r0 top locked
SW3 "PB SW" Switch-PB-6.2x6.3mm-SMD 105.653,4.502 r180 top locked
SW4 "PB SW" Switch-PB-6.2x6.3mm-SMD 115.915,4.502 r180 top locked
SW5 "PB SW" Switch-PB-6.2x6.3mm-SMD 77.292,4.502 r180 top
SW6 "MKH-22D14-G2-B" MKH-22D14-G2-B 104.369,57.988 r180 top
SW7 "Switch" CJS-120xA 82.55,43.815 r0 top
SW8 "MKH-22D14-G2-B" MKH-22D14-G2-B 5.528,5.359 r0 top
SW9 "JS203011JCQN" Switch-Slide-J-Lead-DP3T-13x3.5mm 23.749,38.506 r0 top locked
SW10 "CAS-220TA" CAS-220TA 20.625,4.064 r180 top
SW11 "Switch" CJS-120xA 45.1,19.5 r180 top
TP1 "Ø1.0mm,SMD" TP_SMD_D1.0mm 65.786,19.05 r90 top
TP2 "Ø1.0mm,SMD" TP_SMD_D1.0mm 65.786,21.59 r90 top
TP3 "Ø1.0mm,SMD" TP_SMD_D1.0mm 68.326,19.05 r90 top
TP4 "Ø1.0mm,SMD" TP_SMD_D1.0mm 68.326,21.59 r90 top
TP5 "Ø1.0mm,SMD" TP_SMD_D1.0mm 53.34,16.51 r90 top
TP6 "Ø1.0mm,SMD" TP_SMD_D1.0mm 55.88,16.51 r90 top
TP7 "Ø1.0mm,SMD" TP_SMD_D1.0mm 53.34,19.05 r90 top
TP8 "Ø1.0mm,SMD" TP_SMD_D1.0mm 55.88,19.05 r90 top
TP9 "Ø1.0mm,SMD" TP_SMD_D1.0mm 12.344,31.901 r90 top
TP10 "Ø1.0mm,SMD" TP_SMD_D1.0mm 10.566,32.259 r90 top
TP11 "Ø1.0mm,SMD" TP_SMD_D1.0mm 10.16,35.56 r90 top locked
TP12 "Ø1.0mm,SMD" TP_SMD_D1.0mm 10.16,38.1 r90 top locked
TP13 "Ø1.5mm,SMD" TP_SMD_D1.5mm 93.294,16.129 r0 top
TP14 "Ø1.5mm,SMD" TP_SMD_D1.5mm 95.199,16.129 r0 top
TP15 "Ø1.5mm,SMD" TP_SMD_D1.5mm 91.389,16.129 r0 top
TP16 "Ø1.5mm,SMD" TP_SMD_D1.5mm 97.104,16.129 r0 top
TP17 "Ø1.0mm,SMD" TP_SMD_D1.0mm 123.444,18.415 r90 top
TP18 "Ø1.0mm,SMD" TP_SMD_D1.0mm 125.984,18.415 r90 top
TP19 "Ø1.0mm,SMD" TP_SMD_D1.0mm 62.484,27.94 r90 top
TP20 "Ø1.0mm,SMD" TP_SMD_D1.0mm 103.378,19.304 r0 top
TP21 "Ø1.0mm,SMD" TP_SMD_D1.0mm 103.378,21.209 r0 top
TP22 "Ø1.0mm,SMD" TP_SMD_D1.0mm 107.772,48.311 r0 top
TP23 "Ø1.0mm,SMD" TP_SMD_D1.0mm 77.216,43.18 r0 top
TP24 "Ø1.0mm,SMD" TP_SMD_D1.0mm 10.795,45.847 r0 top
TP25 "Ø1.0mm,SMD" TP_SMD_D1.0mm 10.795,48.387 r0 top
TP26 "Ø1.0mm,SMD" TP_SMD_D1.0mm 14.175,16.475 r0 top
TP27 "Ø1.0mm,SMD" TP_SMD_D1.0mm 11.75,16.475 r0 top
TP28 "Ø1.0mm,SMD" TP_SMD_D1.0mm 14.757,22.682 r0 top
TP29 "Ø1.0mm,SMD" TP_SMD_D1.0mm 22.352,16.383 r0 top
TP30 "Ø1.0mm,SMD" TP_SMD_D1.0mm 28.55,15.037 r270 top
TP31 "Ø1.0mm,SMD" TP_SMD_D1.0mm 21.59,30.988 r90 top
TP32 "Ø1.0mm,SMD" TP_SMD_D1.0mm 21.59,29.21 r0 top
TP33 "Ø1.0mm,SMD" TP_SMD_D1.0mm 31.496,37.338 r0 top
TP34 "Ø1.0mm,SMD" TP_SMD_D1.0mm 28.702,17.78 r0 top
TP35 "Ø1.0mm,SMD" TP_SMD_D1.0mm 61.722,39.624 r0 top
TP36 "Ø1.0mm,SMD" TP_SMD_D1.0mm 69.215,38.1 r0 top
TP37 "Ø1.0mm,SMD" TP_SMD_D1.0mm 71.755,15.24 r0 top
TP38 "Ø1.0mm,SMD" TP_SMD_D1.0mm 86.36,15.24 r0 top
TP39 "Ø1.0mm,SMD" TP_SMD_D1.0mm 69.215,40.005 r0 top
TP40 "TP" TESTPAD-TH 125.095,60.96 r0 top
TP41 "TP" TESTPAD-TH 67.945,5.715 r0 top
TP42 "Ø1.0mm,SMD" TP_SMD_D1.0mm 95.885,25.781 r0 top
TP43 "Ø1.0mm,SMD" TP_SMD_D1.0mm 95.885,27.686 r0 top
TP44 "Ø1.0mm,SMD" TP_SMD_D1.0mm 97.79,25.781 r0 top
TP45 "Ø1.0mm,SMD" TP_SMD_D1.0mm 97.79,27.686 r0 top
TP46 "Ø1.0mm,SMD" TP_SMD_D1.0mm 99.695,25.781 r0 top
TP47 "Ø1.0mm,SMD" TP_SMD_D1.0mm 99.695,27.686 r0 top
TP48 "Ø1.5mm,SMD" TP_SMD_D1.5mm 61.087,38.656 r180 bottom
TP49 "Ø1.5mm,SMD" TP_SMD_D1.5mm 61.087,41.656 r180 bottom
TP50 "Ø1.5mm,SMD" TP_SMD_D1.5mm 58.087,38.656 r180 bottom
TP51 "Ø1.5mm,SMD" TP_SMD_D1.5mm 61.087,44.656 r180 bottom
U1 "nRF52840-QIAA" AQFN50P700X700X85_HS-74N 115.164,37.617 r0 top locked
U2 "nRF5340-QKAA" AQFN40P700X700X85_HS-99N 38.239,30.027 r0 top
U3 "MX25R6435F" SON127P600X80_HS-9N 113.919,23.673 r180 top locked
U4 "TCK106AG" BGA4C40P2X2_76X76X62 107.744,52.676 r180 top
U5 "FSA2466UMX" XQFN40P180X260X50-16N 73.939,19.71 r90 top
U6 "FSA2466UMX" XQFN40P180X260X50-16N 59.792,18.567 r180 top
U7 "FSA2466UMX" XQFN40P180X260X50-16N 81.94,19.71 r90 top locked
U8 "FSA2466UMX" XQFN40P180X260X50-16N 91.948,23.622 r180 top locked
U9 "TCK106AG" BGA4C40P2X2_76X76X62 53.25,41.25 r270 top
U10 "TCK106AG" BGA4C40P2X2_76X76X62 84.925,12.575 r270 top
U11 "XC9236" USP-6C 20.726,20.218 r0 top
U12 "XC9148" USP-6C 12.85,25.5 r270 top
U13 "TCK106AG" BGA4C40P2X2_76X76X62 20.498,15.977 r0 top
U14 "TCK106AG" BGA4C40P2X2_76X76X62 20.498,14.567 r0 top
U15 "TCK106AG" BGA4C40P2X2_76X76X62 20.498,13.157 r0 top
U16 "TCK106AG" BGA4C40P2X2_76X76X62 25.578,17.882 r180 top
U17 "TCK106AG" BGA4C40P2X2_76X76X62 23.317,17.882 r180 top
U18 "TCK106AG" BGA4C40P2X2_76X76X62 30.119,17.186 r180 top
U19 "TS27L2IPT" TSOP65P640X120-8N 24.943,25.781 r0 top
U20 "74LVC1G08" SOT65P210X100-5N 26.416,14.605 r180 top
U21 "74LVC1G11" SOT65P210X100-6N 18.821,10.414 r270 top
U24 "TCK106AG" BGA4C40P2X2_76X76X62 27.483,30.353 r270 top
U25 "74LVC1G08" SOT65P210X100-5N 24.511,10.414 r90 top
U26 "74LVC1G11" SOT65P210X100-6N 21.666,10.414 r270 top
X1 "32MHz" BT-XTAL_2016 119.425,43.713 r180 top
X2 "32.768kHz" XTAL_3215 108.671,38.525 r0 top
X3 "32MHz" BT-XTAL_2016 42.7,37.25 r270 top

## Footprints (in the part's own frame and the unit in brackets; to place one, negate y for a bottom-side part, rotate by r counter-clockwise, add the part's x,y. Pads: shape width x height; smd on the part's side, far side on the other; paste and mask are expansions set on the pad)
AQFN40P700X700X85_HS-99N [mm] "AQFN, 98-Leads, Body 7.00x7.00mm, Pitch 0.40mm, Thermal Pad 5.4x5.0mm, IPC Medium Density"
  rect 5.4x5 smd paste-5 mask+0.05: 104(0.2,0)
  round 0.4 smd paste+0.012 mask+0.05: A1(-3.2,3.2) A31(3.2,3.2) AL1(-3.2,-3.2) AL31(3.2,-3.2)
  round 0.225 smd paste+0.012 mask+0.05: A5(-2.2,3.2) A13(-0.6,3.2) A15(-0.2,3.2) A17(0.2,3.2) A19(0.6,3.2) A21(1,3.2) A23(1.4,3.2) A25(1.8,3.2) A27(2.2,3.2) AA1(-3.2,-1) AA31(3.2,-1) AB2(-2.8,-1.2) AC1(-3.2,-1.4) AC31(3.2,-1.4) AD2(-2.8,-1.6) AE1(-3.2,-1.8) AE31(3.2,-1.8) AF2(-2.8,-2) AG1(-3.2,-2.2) AG31(3.2,-2.2) AH2(-2.8,-2.4) AJ1(-3.2,-2.6) AJ31(3.2,-2.6) AK2(-2.8,-2.8) AK4(-2.4,-2.8) AK6(-2,-2.8) AK8(-1.6,-2.8) AK10(-1.2,-2.8) AK12(-0.8,-2.8) AK14(-0.4,-2.8) AK16(0,-2.8) AK18(0.4,-2.8) AK20(0.8,-2.8) AK22(1.2,-2.8) AK24(1.6,-2.8) AK26(2,-2.8) AK28(2.4,-2.8) AK30(2.8,-2.8) AL3(-2.6,-3.2) AL5(-2.2,-3.2) AL7(-1.8,-3.2) AL9(-1.4,-3.2) AL11(-1,-3.2) AL13(-0.6,-3.2) AL15(-0.2,-3.2) AL17(0.2,-3.2) AL19(0.6,-3.2) AL21(1,-3.2) AL23(1.4,-3.2) AL25(1.8,-3.2) AL27(2.2,-3.2) AL29(2.6,-3.2) B2(-2.8,2.8) B4(-2.4,2.8) B6(-2,2.8) B8(-1.6,2.8) B10(-1.2,2.8) B12(-0.8,2.8) B14(-0.4,2.8) B16(0,2.8) B18(0.4,2.8) B20(0.8,2.8) B22(1.2,2.8) B24(1.6,2.8) B26(2,2.8) B28(2.4,2.8) B30(2.8,2.8) C1(-3.2,2.6) C31(3.2,2.6) D2(-2.8,2.4) E1(-3.2,2.2) E31(3.2,2.2) F2(-2.8,2) G1(-3.2,1.8) G31(3.2,1.8) H2(-2.8,1.6) J1(-3.2,1.4) J31(3.2,1.4) K2(-2.8,1.2) L1(-3.2,1) L31(3.2,1) M2(-2.8,0.8) N1(-3.2,0.6) N31(3.2,0.6) P2(-2.8,0.4) R1(-3.2,0.2) R31(3.2,0.2) T2(-2.8,0) U1(-3.2,-0.2) U31(3.2,-0.2) V2(-2.8,-0.4) W1(-3.2,-0.6) W31(3.2,-0.6) Y2(-2.8,-0.8)
  rrect15% 1.1x1 on Top Paste: ""(-1.75,-1.8) ""(-1.75,-0.6) ""(-1.75,0.6) ""(-1.75,1.8) ""(-0.45,-1.8) ""(-0.45,-0.6) ""(-0.45,0.6) ""(-0.45,1.8) ""(0.85,-1.8) ""(0.85,-0.6) ""(0.85,0.6) ""(0.85,1.8) ""(2.15,-1.8) ""(2.15,-0.6) ""(2.15,0.6) ""(2.15,1.8)
  silkscreen extent -4.22,-3.6 3.6,3.6, body extent -3.5,-3.5 3.5,3.5, height 0.85
AQFN50P700X700X85_HS-74N [mm] "AQFN, 73-Leads, Body 7.00x7.00mm, Pitch 0.50mm, Thermal Pad 4.95x4.95mm, IPC Medium Density"
  rect 4.85x4.85 smd mask+0.05: 74(0,0)
  round 0.275 smd paste+0.012 mask+0.05: A8(-1.25,3.25) A10(-0.75,3.25) A12(-0.25,3.25) A14(0.25,3.25) A16(0.75,3.25) A18(1.25,3.25) A20(1.75,3.25) A22(2.25,3.25) A23(2.75,3.25) AA24(3.25,-2.25) AB2(-2.75,-2.5) AC5(-2,-2.75) AC9(-1,-2.75) AC11(-0.5,-2.75) AC13(0,-2.75) AC15(0.5,-2.75) AC17(1,-2.75) AC19(1.5,-2.75) AC21(2,-2.75) AC24(3.25,-2.75) AD2(-2.75,-3.25) AD4(-2.25,-3.25) AD6(-1.75,-3.25) AD8(-1.25,-3.25) AD10(-0.75,-3.25) AD12(-0.25,-3.25) AD14(0.25,-3.25) AD16(0.75,-3.25) AD18(1.25,-3.25) AD20(1.75,-3.25) AD22(2.25,-3.25) AD23(2.75,-3.25) B1(-3.25,2.75) B3(-2.5,2.75) B5(-2,2.75) B7(-1.5,2.75) B9(-1,2.75) B11(-0.5,2.75) B13(0,2.75) B15(0.5,2.75) B17(1,2.75) B19(1.5,2.75) B24(3.25,2.75) C1(-3.25,2.25) D2(-2.75,2) D23(2.75,2) E24(3.25,1.75) F2(-2.75,1.5) F23(2.75,1.5) G1(-3.25,1.25) H2(-2.75,1) H23(2.75,1) J1(-3.25,0.75) J24(3.25,0.75) K2(-2.75,0.5) L1(-3.25,0.25) L24(3.25,0.25) M2(-2.75,0) N1(-3.25,-0.25) N24(3.25,-0.25) P2(-2.75,-0.5) P23(2.75,-0.5) R1(-3.25,-0.75) R24(3.25,-0.75) T2(-2.75,-1) T23(2.75,-1) U1(-3.25,-1.25) U24(3.25,-1.25) V23(2.75,-1.5) W1(-3.25,-1.75) W24(3.25,-1.75) Y2(-2.75,-2) Y23(2.75,-2)
  silkscreen extent -4.56,-3.6 3.6,3.6, body extent -3.5,-3.5 3.5,3.5, height 0.87
BGA4C40P2X2_76X76X62 [mm] "BGA, 4-Leads, Body 0.8x0.8mm,  Pitch 0.40mm"
  round 0.235 smd mask+0.04: A1(-0.2,0.2) A2(0.2,0.2) B1(-0.2,-0.2) B2(0.2,-0.2)
  silkscreen extent -0.74,-0.45 0.45,0.74, body extent -0.39,-0.39 0.4,0.4, height 0.55
BT-XTAL_2016 [mm] "Crystal 2.0 x 1.6 mm"
  rect 0.95x0.85 smd: 1(-0.725,-0.575) 2(0.725,-0.575) 3(0.725,0.575) 4(-0.725,0.575)
  silkscreen extent -1.08,-0.88 1.08,0.88, body extent -1.05,-0.85 1.05,0.85, height 0.56
CAPC0603X03L_C [mm] "Chip Capacitor, 2-Leads, Body 0.6x0.3mm, IPC High Density"
  rect 0.27x0.3 smd mask+0.05: 1(-0.285,0) 2(0.285,0)
  silkscreen extent -0.49,-0.22 0.49,0.22, body extent -0.3,-0.15 0.3,0.15, height 0.3
CAPC0603X03L_C_NC [mm] "Chip Capacitor, 2-Leads, Body 0.6x0.3mm, IPC High Density"
  rect 0.27x0.3 smd mask+0.05: 1(-0.285,0) 2(0.285,0)
  silkscreen extent -0.49,-0.22 0.49,0.22
CAPC1005X04L [mm] "Chip Capacitor, 2-Leads, Body 1.0x0.5mm, IPC High Density"
  rect 0.6x0.5 smd: 1(-0.5,0) 2(0.5,0)
  silkscreen extent -0.9,-0.35 0.9,0.35, body extent -0.5,-0.25 0.5,0.25, height 0.5
CAPC1005X04L_NC [mm] "Chip Capacitor, 2-Leads, Body 1.0x0.5mm, IPC High Density"
  rect 0.6x0.5 smd: 1(-0.5,0) 2(0.5,0)
  silkscreen extent -0.9,-0.35 0.9,0.35
CAPC1608X06L [mm] "Chip Capacitor, 2-Leads, Body 1.6x0.8mm, IPC High Density"
  rect 0.75x0.8 smd: 1(-0.675,0) 2(0.675,0)
  silkscreen extent -1.17,-0.5 1.17,0.5, body extent -0.8,-0.4 0.8,0.4, height 0.8
CAPC1608X06L_NC [mm] "Chip Capacitor, 2-Leads, Body 1.6x0.8mm, IPC High Density"
  rect 0.75x0.8 smd: 1(-0.675,0) 2(0.675,0)
  silkscreen extent -1.17,-0.5 1.17,0.5
CAPC2012X11L [mm] "Chip Capacitor, 2-Leads, Body 2.0x1.3mm, IPC High Density"
  rect 1.1x1.4 smd: 1(-0.75,0) 2(0.75,0)
  silkscreen extent -1.43,-0.8 1.42,0.8, body extent -1,-0.62 1,0.63, height 1.25
CAS-220TA [mm] "SLIDE SWITCH DPDT J HOOK"
  rect 1x1.6 smd: 1(-1.75,-1.85) 2(0,-1.85) 3(1.75,-1.85) 4(-1.75,1.85) 5(0,1.85) 6(1.75,1.85)
  silkscreen extent -2.8,-2.6 2.7,2, body extent -2.7,-2.15 2.7,2.16, height 2.51
CJS-120xA [mm] "Slide Switches - SPDT, SMD, ON-ON"
  rect 1x1.6 smd: 1(1.75,-1.15) 2(0,1.15) 3(-1.75,-1.15)
  silkscreen extent -3,-1.25 3,1.25, body extent -3,-1.4 3,1.45, height 2.5
COAXIAL-SWF [mm]
  rect 0.5x0.58 smd: 1(0,1.16) 3(0,-1.16)
  rect 0.75x0.8 smd: 2(-1.025,-0.95) 2(-1.025,0.95) 2(1.025,-0.95) 2(1.025,0.95)
  Top Layer pour cut-out: -0.65,0.55 0.65,0.55 0.65,1.35 -0.65,1.35
  Top Layer pour cut-out: 0.65,-0.55 -0.65,-0.55 -0.65,-1.35 0.65,-1.35
  silkscreen extent -1.25,-1.25 1.25,1.25, body extent -1.26,-1.3 1.26,1.3, height 1.55
DFN65P100X40-3L [mm] "DFN, 3-Leads, Body 0.60x1.00mm, Pitch 0.65mm, IPC High Density"
  rect 0.4x0.25 smd mask+0.05: 1(-0.35,0.225) 2(-0.35,-0.225)
  rect 0.4x0.7 smd mask+0.065: 3(0.35,0)
  silkscreen extent -0.57,0.57 -0.48,0.67, body extent -0.53,-0.33 0.53,0.33, height 0.4
DFN65P200X200X80_HS-6N [mm] "DFN, 6-Leads, Body 2.00x2.00mm, Pitch 0.65mm, IPC Medium Density"
  rect 0.45x0.42 smd mask+0.055: 1(-0.905,0.65) 2(-0.905,0) 3(-0.905,-0.65) 4(0.905,-0.65) 5(0.905,0) 6(0.905,0.65)
  rect 0.92x0.71 smd mask+0.055: 3(0,-0.475) 6(0,0.475)
  silkscreen extent -1.47,-1.06 1.06,1.27, body extent -1.05,-1.05 1.05,1.05, height 0.65
Fiducial [mm] "Fiducial Mark"
  round 1 smd paste-2539.97 mask+0.5: 0(0,0)
  round 1 smd far side paste-2539.97 mask+0.5: 0(0,0)
  Top Layer keep-out circle w0.01: c0,0 r1
  Bottom Layer keep-out circle w0.01: c0,0 r1
FPC_05P-0.5mm-RA-SMD [mm] "FPC, 5-Leads, Pitch 0,5mm"
  rect 0.6x2.6 smd: 0(-0.9,-2.3) 0(2.9,-2.3)
  rect 0.3x0.8 smd mask+0.05: 1(0,0) 2(0.5,0) 3(1,0) 4(1.5,0) 5(2,0)
  silkscreen extent -1.38,-3.93 3.38,0.08, body extent -1.3,-3.85 3.3,0.2, height 1.2
HDR_2x3-SMD [mil] "Board-Board Conn, Header, 6-way, 2-row"
  rect 40x113 smd: 1(-100,-100) 2(-100,100) 3(0,-100) 4(0,100) 5(100,-100) 6(100,100)
  silkscreen extent -155,-135 150,100, body extent -150,-148 150,148, height 382
HDR_2x5-SMD-1.27mm-K [mm] "SMT MICRO HEADER, (1,27) .050\" Keying Shroud"
  rect 0.76x2.4 smd: 1(-2.54,-1.95) 2(-2.54,1.95) 3(-1.27,-1.95) 4(-1.27,1.95) 5(0,-1.95) 6(0,1.95) 7(1.27,-1.95) 8(1.27,1.95) 9(2.54,-1.95) 10(2.54,1.95)
  silkscreen extent -3.56,-2.38 3.25,1.75, body extent -3.14,-2.92 3.14,2.92, height 6.11
HDR_2x6-NC [mm] "Pin Header, 2.54mm through hole"
  rect 1.5x1.5 hole 0.9: 1(-6.35,-1.27)
  round 1.5 hole 0.9: 2(-6.35,1.27) 3(-3.81,-1.27) 4(-3.81,1.27) 5(-1.27,-1.27) 6(-1.27,1.27) 7(1.27,-1.27) 8(1.27,1.27) 9(3.81,-1.27) 10(3.81,1.27) 11(6.35,-1.27) 12(6.35,1.27)
  silkscreen extent -7.62,-2.54 7.62,2.54
HDR_2x8-NC [mm] "Pin Header, 2.54mm through hole"
  rect 1.5x1.5 hole 0.9: 1(-8.89,-1.27)
  round 1.5 hole 0.9: 2(-8.89,1.27) 3(-6.35,-1.27) 4(-6.35,1.27) 5(-3.81,-1.27) 6(-3.81,1.27) 7(-1.27,-1.27) 8(-1.27,1.27) 9(1.27,-1.27) 10(1.27,1.27) 11(3.81,-1.27) 12(3.81,1.27) 13(6.35,-1.27) 14(6.35,1.27) 15(8.89,-1.27) 16(8.89,1.27)
  silkscreen extent -10.16,-2.54 10.16,2.54
HDR_2x10-NC [mm] "Pin Header, 2.54mm through hole"
  rect 1.5x1.5 hole 0.9: 1(-11.43,-1.27)
  round 1.5 hole 0.9: 2(-11.43,1.27) 3(-8.89,-1.27) 4(-8.89,1.27) 5(-6.35,-1.27) 6(-6.35,1.27) 7(-3.81,-1.27) 8(-3.81,1.27) 9(-1.27,-1.27) 10(-1.27,1.27) 11(1.27,-1.27) 12(1.27,1.27) 13(3.81,-1.27) 14(3.81,1.27) 15(6.35,-1.27) 16(6.35,1.27) 17(8.89,-1.27) 18(8.89,1.27) 19(11.43,-1.27) 20(11.43,1.27)
  silkscreen extent -12.7,-2.54 12.7,2.54
HDR_2x10-SMD-1.27mm-NC [mm] "SMT MICRO HEADER, (1,27) .050\""
  rect 0.76x2.4 smd paste-2: 1(-5.715,-1.95) 2(-5.715,1.95) 3(-4.445,-1.95) 4(-4.445,1.95) 5(-3.175,-1.95) 6(-3.175,1.95) 7(-1.905,-1.95) 8(-1.905,1.95) 9(-0.635,-1.95) 10(-0.635,1.95) 11(0.635,-1.95) 12(0.635,1.95) 13(1.905,-1.95) 14(1.905,1.95) 15(3.175,-1.95) 16(3.175,1.95) 17(4.445,-1.95) 18(4.445,1.95) 19(5.715,-1.95) 20(5.715,1.95)
  silkscreen extent -6.73,-2.38 6.43,1.75
INDC1005X04L [mm] "Chip Inductor, 2-Leads, Body 1.0x0.5mm, IPC High Density"
  rect 0.65x0.5 smd: 1(-0.475,0) 2(0.475,0)
  silkscreen extent -0.9,-0.35 0.9,0.35, body extent -0.5,-0.25 0.5,0.25, height 0.5
INDC1608X06L [mm] "Chip Inductor, 2-Leads, Body 1.6x0.8mm, IPC High Density"
  rect 0.75x0.8 smd: 1(-0.675,0) 2(0.675,0)
  silkscreen extent -1.17,-0.5 1.17,0.5, body extent -0.8,-0.4 0.8,0.4, height 0.8
L-KLS5-CR2032-23-B1 [mm] "SMT,CR2032 Coin Battery Holder"
  rect 3.2x4.2 smd: 1(-14.65,0) 2(14.65,0)
  silkscreen extent -16,-8 14.42,8, body extent -15.7,-8 15.85,8, height 5.17
LED_0603_G [mil] "SMD Super Bright LED, GREEN"
  rect 30x32 smd: 1(-27.5,0) 2(27.5,0)
  silkscreen extent -58,-20 48,20, body extent -32,-16 32,16, height 24
LIST_1x2-NC [mm] "Pin List, 2.54mm through hole"
  rect 1.5x1.5 hole 0.9: 1(-1.27,0)
  round 1.5 hole 0.9: 2(1.27,0)
  silkscreen extent -2.54,-1.27 2.54,1.27
LIST_1x3-NC [mm] "Pin List, 2.54mm through hole"
  rect 1.5x1.5 hole 0.9: 1(-2.54,0)
  round 1.5 hole 0.9: 2(0,0) 3(2.54,0)
  silkscreen extent -3.81,-1.27 3.81,1.27
LIST_1x6_SMD-NC [mm] "Pin List, 2.54mm, SMD"
  rect 1.02x2.19 smd: 1(0,-1.465) 1(0,1.465) 2(2.54,-1.465) 2(2.54,1.465) 3(5.08,-1.465) 3(5.08,1.465) 4(7.62,-1.465) 4(7.62,1.465) 5(10.16,-1.465) 5(10.16,1.465) 6(12.7,-1.465) 6(12.7,1.465)
  silkscreen extent -1.27,-1.27 13.97,1.27
LIST_1x8_SMD-NC [mm] "Pin List, 2.54mm, SMD"
  rect 1.02x2.19 smd: 1(0,-1.465) 1(0,1.465) 2(2.54,-1.465) 2(2.54,1.465) 3(5.08,-1.465) 3(5.08,1.465) 4(7.62,-1.465) 4(7.62,1.465) 5(10.16,-1.465) 5(10.16,1.465) 6(12.7,-1.465) 6(12.7,1.465) 7(15.24,-1.465) 7(15.24,1.465) 8(17.78,-1.465) 8(17.78,1.465)
  silkscreen extent -1.27,-1.27 19.05,1.27
LIST_1x10_SMD-NC [mm] "Pin List, 2.54mm, SMD"
  rect 1.02x2.19 smd: 1(0,-1.465) 1(0,1.465) 2(2.54,-1.465) 2(2.54,1.465) 3(5.08,-1.465) 3(5.08,1.465) 4(7.62,-1.465) 4(7.62,1.465) 5(10.16,-1.465) 5(10.16,1.465) 6(12.7,-1.465) 6(12.7,1.465) 7(15.24,-1.465) 7(15.24,1.465) 8(17.78,-1.465) 8(17.78,1.465) 9(20.32,-1.465) 9(20.32,1.465) 10(22.86,-1.465) 10(22.86,1.465)
  silkscreen extent -1.27,-1.27 24.13,1.27
LIST_1x13_SMD [mm] "Pin List, 2.54mm, SMD"
  rect 1.02x2.19 smd: 1(0,-1.465) 1(0,1.465) 2(2.54,-1.465) 2(2.54,1.465) 3(5.08,-1.465) 3(5.08,1.465) 4(7.62,-1.465) 4(7.62,1.465) 5(10.16,-1.465) 5(10.16,1.465) 6(12.7,-1.465) 6(12.7,1.465) 7(15.24,-1.465) 7(15.24,1.465) 8(17.78,-1.465) 8(17.78,1.465) 9(20.32,-1.465) 9(20.32,1.465) 10(22.86,-1.465) 10(22.86,1.465) 11(25.4,-1.465) 11(25.4,1.465) 12(27.94,-1.465) 12(27.94,1.465) 13(30.48,-1.465) 13(30.48,1.465)
  silkscreen extent -1.27,-1.27 31.75,1.27, body extent -1.27,-2.5 31.75,2.5, height 9.82
LIST_1x13_SMD-NC [mm] "Pin List, 2.54mm, SMD"
  rect 1.02x2.19 smd: 1(0,-1.465) 1(0,1.465) 2(2.54,-1.465) 2(2.54,1.465) 3(5.08,-1.465) 3(5.08,1.465) 4(7.62,-1.465) 4(7.62,1.465) 5(10.16,-1.465) 5(10.16,1.465) 6(12.7,-1.465) 6(12.7,1.465) 7(15.24,-1.465) 7(15.24,1.465) 8(17.78,-1.465) 8(17.78,1.465) 9(20.32,-1.465) 9(20.32,1.465) 10(22.86,-1.465) 10(22.86,1.465) 11(25.4,-1.465) 11(25.4,1.465) 12(27.94,-1.465) 12(27.94,1.465) 13(30.48,-1.465) 13(30.48,1.465)
  silkscreen extent -1.27,-1.27 31.75,1.27
LIST_ANG_1x2-SMD-2.54MM [mm] "Pin List, 2.54mm, Surface Mount, Angled"
  round 1.7 hole 1.7 unplated: 0(0,-4.496)
  rect 1.02x4 smd: 1(-1.27,0.204) 2(1.27,0.204)
  silkscreen extent -2.54,-11.58 2.54,-2.22, body extent -2.56,-11.61 2.52,1.35, height 3.03
MKH-22D14-G2-B [mm] "Slide Switches - DPDT, SMD, ON-ON"
  rect 1.2x2 smd: 1(2.5,-2.75) 2(0,-2.75) 3(-2.5,-2.75) 4(2.5,2.75) 5(0,2.75) 6(-2.5,2.75)
  silkscreen extent -4.5,-3.75 4.5,1.75, body extent -4.25,-3.75 4.25,2.5, height 3.5
PMCPB5530X [mm] "QFN, 6-Leads, Body 2.00x2.00mm, Pitch 0.65mm, IPC Medium Density"
  rect 0.3x0.35 smd mask+0.05: 1(-0.875,0.65) 2(-0.875,0) 3(-0.875,-0.65) 4(0.875,-0.65) 5(0.875,0) 6(0.875,0.65)
  rect 1.05x0.72 smd mask+0.05: 3(0,-0.49) 6(0,0.49)
  silkscreen extent -1.47,-1.06 1.06,1.27, body extent -1.05,-1.05 1.05,1.05, height 0.65
RESC0603X03L_C [mm] "Chip Resistor, 2-Leads, Body 0.6x0.3mm, IPC High Density"
  rect 0.27x0.3 smd: 1(-0.285,0) 2(0.285,0)
  silkscreen extent -0.49,-0.22 0.49,0.22, body extent -0.3,-0.15 0.3,0.15, height 0.23
RESC0603X03L_C_NC [mm] "Chip Resistor, 2-Leads, Body 0.6x0.3mm, IPC High Density"
  rect 0.27x0.3 smd: 1(-0.285,0) 2(0.285,0)
  silkscreen extent -0.49,-0.22 0.49,0.22
RESC1005X04L [mm] "Chip Resistor, 2-Leads, Body 1.0x0.5mm, IPC High Density"
  rect 0.6x0.55 smd mask+0.05: 1(-0.5,0) 2(0.5,0)
  silkscreen extent -0.87,-0.38 0.88,0.38, body extent -0.5,-0.25 0.5,0.25, height 0.3
RESC1005X04L_NC [mm] "Chip Resistor, 2-Leads, Body 1.0x0.5mm, IPC High Density"
  rect 0.6x0.55 smd mask+0.05: 1(-0.5,0) 2(0.5,0)
  silkscreen extent -0.87,-0.38 0.88,0.38
SM02B-SRSS-TB [mm] "JST, SH connector, side entry SMD, 1mm pitch"
  rect 1.2x1.8 smd: 0(-2.1,-3.875) 0(2.1,-3.875)
  rect 0.6x1.55 smd: 1(-0.5,0) 2(0.5,0)
  silkscreen extent -2.07,-4.67 2.07,-0.3, body extent -2,-4.55 2,0.4, height 2.95
SOCKET_1x6_SMD [mm] "Socket, 2.54mm, SMD"
  rect 1.02x2.19 smd: 1(0,-1.465) 1(0,1.465) 2(2.54,-1.465) 2(2.54,1.465) 3(5.08,-1.465) 3(5.08,1.465) 4(7.62,-1.465) 4(7.62,1.465) 5(10.16,-1.465) 5(10.16,1.465) 6(12.7,1.465) 6(12.7,-1.465)
  silkscreen extent -1.9,-1.27 13.97,1.65, body extent -1.27,-2.29 13.97,2.29, height 7.47
SOCKET_1x8_SMD [mm] "Socket, 2.54mm, SMD"
  rect 1.02x2.19 smd: 1(0,-1.465) 1(0,1.465) 2(2.54,-1.465) 2(2.54,1.465) 3(5.08,-1.465) 3(5.08,1.465) 4(7.62,-1.465) 4(7.62,1.465) 5(10.16,-1.465) 5(10.16,1.465) 6(12.7,1.465) 6(12.7,-1.465) 7(15.24,-1.465) 7(15.24,1.465) 8(17.78,-1.465) 8(17.78,1.465)
  silkscreen extent -1.9,-1.27 19.05,1.65, body extent -1.27,-2.29 19.05,2.29, height 7.47
SOCKET_1x10_SMD [mm] "Socket, 2.54mm, SMD"
  rect 1.02x2.19 smd: 1(0,1.465) 1(0,-1.465) 2(2.54,-1.465) 2(2.54,1.465) 3(5.08,-1.465) 3(5.08,1.465) 4(7.62,-1.465) 4(7.62,1.465) 5(10.16,-1.465) 5(10.16,1.465) 6(12.7,-1.465) 6(12.7,1.465) 7(15.24,-1.465) 7(15.24,1.465) 8(17.78,-1.465) 8(17.78,1.465) 9(20.32,-1.465) 9(20.32,1.465) 10(22.86,-1.465) 10(22.86,1.465)
  silkscreen extent -1.91,-1.27 24.13,1.65, body extent -1.27,-2.29 24.13,2.29, height 7.47
SOCKET_2x3_SMD-2.54mm-NC [mm] "Socket, 2.54mm, SMD"
  rect 1.02x2.22 smd: 1(2.54,-2.825) 2(2.54,2.825) 3(0,-2.825) 4(0,2.825) 5(-2.54,-2.825) 6(-2.54,2.825)
  silkscreen extent -3.81,-3.3 3.81,2.54
SOCKET_2x9_SMD-2.54mm-Mirrored [mil] "CONN HEADER VERT DUAL 18POS SMD - FEMALE HEADER, PCB, 0.1\", 10+10WAY"
  rect 50x150 smd: 1(-400,-87.5) 2(-400,87.5) 3(-300,-87.5) 4(-300,87.5) 5(-200,-87.5) 6(-200,87.5) 7(-100,-87.5) 8(-100,87.5) 9(0,-87.5) 10(0,87.5) 11(100,-87.5) 12(100,87.5) 13(200,-87.5) 14(200,87.5) 15(300,-87.5) 16(300,87.5) 17(400,-87.5) 18(400,87.5)
  silkscreen extent -450,-130 450,100, body extent -450,-138 450,139, height 290
SODFL100X40-2N [mm] "SODFL, 2-Leads, Body 0.60x1.00mm, IPC Medium Density"
  rect 0.36x0.25 smd: 1(-0.42,0) 2(0.42,0)
  silkscreen extent -0.7,-0.35 0.5,0.5, body extent -0.5,-0.33 0.5,0.33, height 0.4
SODFL500X108-2N [mm] "SODFL, 2-Leads, Body 2.70x5.00mm, IPC Medium Density"
  rect 1.3x1.75 smd: 1(-2.05,0) 2(2.05,0)
  silkscreen extent -2.9,-1.4 2.15,1.43, body extent -2.5,-1.4 2.5,1.4, height 1.08
Solderbridge [mil]
  round 1 smd paste-99999: 1(-13.78,0) 2(13.78,0)
  Top Layer region: 7.49,-19.36 15.76,-15.74 21.55,-8.8 23.62,0 23.62,0 21.55,8.79 15.76,15.74 7.49,19.36 7.49,19.36 6.18,19.31 5.02,18.71 4.22,17.68 3.94,16.4 3.94,16.4 3.94,-16.4 4.22,-17.68 5.02,-18.71 6.18,-19.31 7.49,-19.36
  Top Layer region: -7.49,19.36 -15.76,15.74 -21.55,8.8 -23.62,0 -23.62,0 -21.55,-8.79 -15.76,-15.74 -7.49,-19.36 -7.49,-19.36 -6.18,-19.31 -5.02,-18.71 -4.22,-17.68 -3.94,-16.4 -3.94,-16.4 -3.94,16.4 -4.22,17.68 -5.02,18.71 -6.18,19.31 -7.49,19.36
Solderbridge_Shorted [mil]
  round 1 smd paste-99999: 1(-13.78,0) 2(13.78,0)
  Top Layer region: -4.92,3.94 -4.92,-3.94 4.92,-3.94 4.92,3.94
  Top Layer region: -7.49,19.36 -15.76,15.74 -21.55,8.8 -23.62,0 -23.62,0 -21.55,-8.79 -15.76,-15.74 -7.49,-19.36 -7.49,-19.36 -6.18,-19.31 -5.02,-18.71 -4.22,-17.68 -3.94,-16.4 -3.94,-16.4 -3.94,16.4 -4.22,17.68 -5.02,18.71 -6.18,19.31 -7.49,19.36
  Top Layer region: 7.49,-19.36 15.76,-15.74 21.55,-8.8 23.62,0 23.62,0 21.55,8.79 15.76,15.74 7.49,19.36 7.49,19.36 6.18,19.31 5.02,18.71 4.22,17.68 3.94,16.4 3.94,16.4 3.94,-16.4 4.22,-17.68 5.02,-18.71 6.18,-19.31 7.49,-19.36
SON127P600X80_HS-9N [mm] "SON, 8-Leads, Body 5.00x6.00mm, Pitch 1.27mm, Thermal Pad 4.00x3.40mm, IPC Medium Density"
  rect 1.15x0.45 smd: 1(-2.77,1.905) 2(-2.77,0.635) 3(-2.77,-0.635) 4(-2.77,-1.905) 5(2.77,-1.905) 6(2.77,-0.635) 7(2.77,0.635) 8(2.77,1.905)
  rect 3.4x4 smd paste-1.7: 9(0,0)
  silkscreen extent -3.98,-2.6 3.1,2.67, body extent -3.05,-2.55 3.05,2.55, height 0.8
SOT65P210X100-5N [mm] "SOT23, 5-Leads, Body 2,2x2,4mm (max), Pitch 0,65mm, IPC Medium Density"
  rect 0.9x0.35 smd: 1(-0.95,0.65) 2(-0.95,0) 3(-0.95,-0.65) 4(0.95,-0.65) 5(0.95,0.65)
  silkscreen extent -1.08,-1.1 0.1,1.5, body extent -1.1,-1 1.1,1, height 0.97
SOT65P210X100-6N [mm] "SOT23, 6-Leads, Body 2,2x2,4mm (max), Pitch 0,65mm, IPC Medium Density"
  rect 0.9x0.35 smd: 1(-0.95,0.65) 2(-0.95,0) 3(-0.95,-0.65) 4(0.95,-0.65) 5(0.95,0) 6(0.95,0.65)
  silkscreen extent -1.07,-1.1 0.1,1.5, body extent -1.05,-1 1.05,1, height 0.92
SOT89-150P409X160-3N [mm] "SOT89, 3-Leads, Body 4.50x2.45mm, Pitch 1.50mm, Lead Span 4.1mm, IPC Medium Density"
  rect 1.4x0.6 smd: 1(-1.8,1.5) 3(-1.8,-1.5)
  rect 1.7x0.6 smd: 2(-1.65,0)
  Top Layer region: -1.016,-0.3 -0.635,-0.3 -0.635,0.3 -1.016,0.3
  Top Layer region: -0.8,0.3 -0.15,0.95 1.85,0.95 2.5,0.3 2.5,-0.3 1.85,-0.95 -0.15,-0.95 -0.8,-0.3
  silkscreen extent -2.05,-2.3 1.32,2.47, body extent -2.2,-2.3 1.93,2.3, height 1.6
SOT190P230X110-4L [mm] "SOT143, 4-Leads, Body 3.0x2.5mm (max), Pitch 1.90mm, IPC High Density"
  rect 0.85x1 smd: 1(-1.025,0.75)
  rect 0.85x0.6 smd: 2(-1.025,-0.95) 3(1.025,-0.95) 4(1.025,0.95)
  silkscreen extent -1.15,-1.5 0.7,1.92, body extent -1.21,-1.46 1.21,1.46, height 1
Switch-PB-6.2x6.3mm-SMD [mm] "6.2×6.5mm TACT Switch, without ground connector"
  rect 2.75x1.4 smd: 1(-3.375,2) 1(3.375,2) 2(-3.375,-2) 2(3.375,-2)
  silkscreen extent -3,-3 3,3, body extent -3.6,-3.1 3.6,3.1, height 2.5
Switch-Slide-J-Lead-DP3T-13x3.5mm [mm] "Slide Switch - DP3T, SMD, ON-ON-ON"
  rect 1.2x1.6 smd: 1(-4,-1.4) 2(-2,-1.4) 3(2,-1.4) 4(4,-1.4) 5(-4,1.4) 6(-2,1.4) 7(2,1.4) 8(4,1.4)
  silkscreen extent -6,-1.75 6,1.75, body extent -6,-1.8 6,1.7, height 5.5
TC2050-IDC-NLFP [mil]
  round 39 hole 39 unplated: 0(-150,0) 0(150,-40) 0(150,40)
  round 31 smd paste-196.85: 1(-100,-25) 2(-50,-25) 3(0,-25) 4(50,-25) 5(100,-25) 6(100,25) 7(50,25) 8(0,25) 9(-50,25) 10(-100,25)
  Top Layer pour cut-out: -100,25 -100,-25 100,-25 100,25
TESTPAD-TH [mm]
  round 1.5 hole 1: 1(0,0)
  silkscreen extent -1,-1 1,1
TP_SMD_D1.0mm [mm] "Test point - pad 1.0mm"
  round 1 smd paste-5: 1(0,0)
  silkscreen extent -0.76,-0.76 0.76,0.76
TP_SMD_D1.5mm [mm] "Test point - pad 1.5mm"
  round 1.5 smd paste-5: 1(0,0)
  silkscreen extent -0.95,-0.95 0.95,0.95, body extent -0.75,-0.75 0.75,0.75, height 0.05
TSOP65P640X120-8N [mm] "TSOP, 8-Leads, Body 3.00x4.40mm, Pitch 0.65mm, IPC Medium Density"
  oval 1.4x0.4 smd: 1(-2.95,0.975) 2(-2.95,0.325) 3(-2.95,-0.325) 4(-2.95,-0.975) 5(2.95,-0.975) 6(2.95,-0.325) 7(2.95,0.325) 8(2.95,0.975)
  silkscreen extent -3.07,-1.55 1.85,1.87, body extent -3.2,-1.55 3.2,1.55, height 1.2
TY-NR3015 [mm] "Molded Inductor, 2-Leads, Body 3.00x3.00mm, IPC Medium Density"
  rect 0.8x2.7 smd: 1(-1.1,0) 2(1.1,0)
  silkscreen extent -2.05,-1.55 1.55,1.75, body extent -1.5,-1.5 1.5,1.5, height 1.35
USB-Micro-B-RA-SMD-PiP_Allen [mm] "Micro USB B SMT"
  rect 1.35x0.4 smd mask+0.075: 1(0,1.3) 2(0,0.65) 3(0,0) 4(0,-0.65) 5(0,-1.3)
  oval 2.15x1 hole 0.45 slot 1.5 at 0 deg paste-2539.97: 6(-2.675,-3.2) 6(-2.675,3.2)
  oval 2.4x1.4 on Top Paste: 6(-2.675,-3.2) 6(-2.675,3.2)
  rect 1.2x1.8 smd: 6(0.073,-3.25) 6(0.073,3.25)
  silkscreen extent -4.75,-3.75 0.25,3.75, body extent -5.43,-3.93 0.28,3.93, height 2.84
USP-6C [mm] "DFN, 6-Leads, Body 2.00x1.80mm, Pitch 0.50mm, Thermal Pad 1.00x1.40mm, IPC Medium Density"
  rect 0.45x0.35 smd paste-0.05 mask+0.075: 1(-0.975,0.55)
  rect 0.45x0.25 smd paste-0.05 mask+0.075: 2(-0.975,0) 3(-0.975,-0.5) 4(0.975,-0.5) 5(0.975,0) 6(0.975,0.5)
  rect 0.9x1.8 smd paste-2: 7(0,0)
  Top Layer region: -0.5,-0.8 0.5,-0.8 0.5,0.8 -0.5,0.8
  silkscreen extent -1.42,-1.07 0.97,1.12, body extent -0.93,-1.02 0.93,1.02, height 0.6
VLS3012HBX [mm] "4.7µH Shielded Wirewound Inductor 2.23A 201 mOhm Max Nonstandard"
  rect 1x3.4 smd: 1(-1.05,0) 2(1.05,0)
  silkscreen extent -0.37,-1.55 0.38,1.55, body extent -1.53,-1.51 1.53,1.51, height 1.2
XQFN40P180X260X50-16N [mm] "QFN, 16-Leads, Body 1.80x2.60mm, Pitch 0.40mm, IPC Medium Density"
  oval 0.65x0.22 smd paste-0.02 mask+0.04: 1(-0.825,0.6) 2(-0.825,0.2) 3(-0.825,-0.2) 4(-0.825,-0.6) 9(0.825,-0.6) 10(0.825,-0.2) 11(0.825,0.2) 12(0.825,0.6)
  oval 0.22x0.65 smd paste-0.02 mask+0.04: 5(-0.6,-1.225) 6(-0.2,-1.225) 7(0.2,-1.225) 8(0.6,-1.225) 13(0.6,1.225) 14(0.2,1.225) 15(-0.2,1.225) 16(-0.6,1.225)
  silkscreen extent -1.45,-1.4 1,1.4, body extent -0.91,-1.31 0.91,1.31, height 0.55
XTAL_3215 [mm] "XTAL SMD 3.2 x 1.5 mm"
  rect 1x1.8 smd: 1(-1.25,0) 2(1.25,0)
  silkscreen extent -0.6,-0.75 0.6,0.75, body extent -1.6,-0.75 1.6,0.75, height 0.81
